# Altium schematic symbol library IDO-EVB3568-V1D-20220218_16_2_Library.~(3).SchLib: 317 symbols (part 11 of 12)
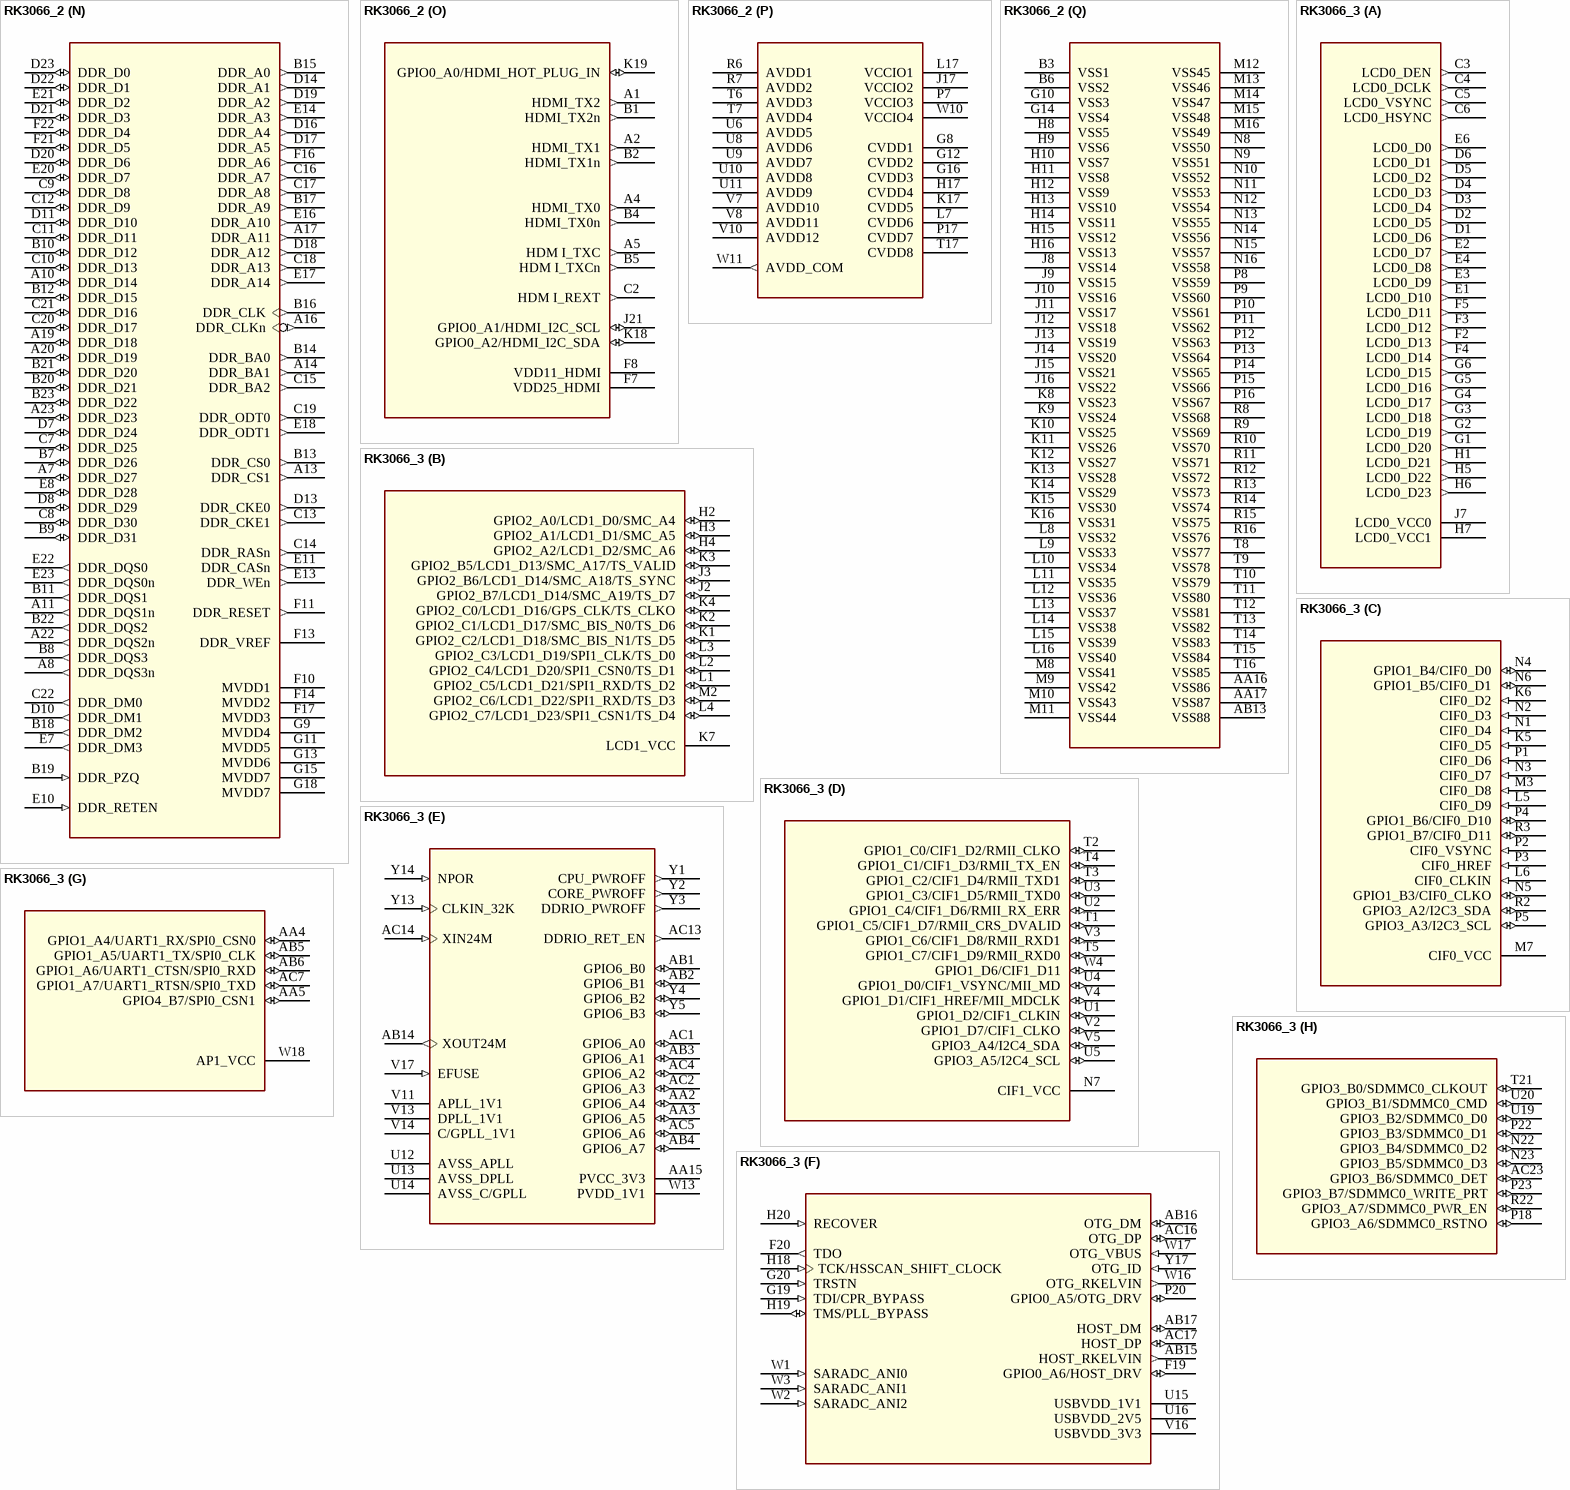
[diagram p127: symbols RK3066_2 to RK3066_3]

## RK3066_2
designator U?
Altium-Right: 120; Altium-Bottom: 230; Altium-Right1: 190; Altium-Bottom1: 200; Altium-Right2: 150; Altium-Bottom2: 250; Altium-Bottom3: 180; Altium-Right4: 160; Altium-Bottom5: 130; Altium-Bottom6: 280; Altium-Bottom7: 310; Altium-Bottom8: 270; Altium-Bottom9: 140; Altium-Bottom11: 530; Altium-Right13: 110; Altium-Bottom13: 170; Altium-Right14: 100; Altium-Bottom14: 470; Altium-Right15: 80; Altium-Bottom15: 350
footprint BGA453
part A pins: C3 LCD0_DEN (out), C4 LCD0_DCLK (out), C5 LCD0_VSYNC (out), C6 LCD0_HSYNC (out), D1 LCD0_D6 (out), D2 LCD0_D5 (out), D3 LCD0_D4 (out), D4 LCD0_D3 (out), D5 LCD0_D2 (out), D6 LCD0_D1 (out), E1 LCD0_D10 (out), E2 LCD0_D7 (out), E3 LCD0_D9 (out), E4 LCD0_D8 (out), E6 LCD0_D0 (out), F2 LCD0_D13 (out), F3 LCD0_D12 (out), F4 LCD0_D14 (out), F5 LCD0_D11 (out), G1 LCD0_D20 (out), G2 LCD0_D19 (out), G3 LCD0_D18 (out), G4 LCD0_D17 (out), G5 LCD0_D16 (out), G6 LCD0_D15 (out), H1 LCD0_D21 (out), H5 LCD0_D22 (out), H6 LCD0_D23 (out), H7 LCD0_VCC1 (power), J7 LCD0_VCC0 (power)
part B pins: H2 GPIO2_A0/LCD1_D0/SMC_A4 (io), H3 GPIO2_A1/LCD1_D1/SMC_A5 (io), H4 GPIO2_A2/LCD1_D2/SMC_A6 (io), J2 GPIO2_B7/LCD1_D14/SMC_A19/TS_D7 (io), J3 GPIO2_B6/LCD1_D14/SMC_A18/TS_SYNC (io), K1 GPIO2_C2/LCD1_D18/SMC_BIS_N1/TS_D5 (io), K2 GPIO2_C1/LCD1_D17/SMC_BIS_N0/TS_D6 (io), K3 GPIO2_B5/LCD1_D13/SMC_A17/TS_VALID (io), K4 GPIO2_C0/LCD1_D16/GPS_CLK/TS_CLKO (io), K7 LCD1_VCC (power), L1 GPIO2_C5/LCD1_D21/SPI1_RXD/TS_D2 (io), L2 GPIO2_C4/LCD1_D20/SPI1_CSN0/TS_D1 (io), L3 GPIO2_C3/LCD1_D19/SPI1_CLK/TS_D0 (io), L4 GPIO2_C7/LCD1_D23/SPI1_CSN1/TS_D4 (io), M2 GPIO2_C6/LCD1_D22/SPI1_RXD/TS_D3 (io)
part C pins: K5 CIF0_D5 (in), K6 CIF0_D2 (in), L5 CIF0_D9 (in), L6 CIF0_CLKIN (in), M3 CIF0_D8 (in), M7 CIF0_VCC (power), N1 CIF0_D4 (in), N2 CIF0_D3 (in), N3 CIF0_D7 (in), N4 GPIO1_B4/CIF0_D0 (io), N5 GPIO1_B3/CIF0_CLKO (io), N6 GPIO1_B5/CIF0_D1 (io), P1 CIF0_D6 (in), P2 CIF0_VSYNC (in), P3 CIF0_HREF (in), P4 GPIO1_B6/CIF0_D10 (io), P5 GPIO3_A3/I2C3_SCL (io), R2 GPIO3_A2/I2C3_SDA (io), R3 GPIO1_B7/CIF0_D11 (io)
part D pins: N7 CIF1_VCC (power), T1 GPIO1_C5/CIF1_D7/RMII_CRS_DVALID (io), T2 GPIO1_C0/CIF1_D2/RMII_CLKO (io), T3 GPIO1_C2/CIF1_D4/RMII_TXD1 (io), T4 GPIO1_C1/CIF1_D3/RMII_TX_EN (io), T5 GPIO1_C7/CIF1_D9/RMII_RXD0 (io), U1 GPIO1_D2/CIF1_CLKIN (io), U2 GPIO1_C4/CIF1_D6/RMII_RX_ERR (io), U3 GPIO1_C3/CIF1_D5/RMII_TXD0 (io), U4 GPIO1_D0/CIF1_VSYNC/MII_MD (io), U5 GPIO3_A5/I2C4_SCL (io), V2 GPIO1_D7/CIF1_CLKO (io), V3 GPIO1_C6/CIF1_D8/RMII_RXD1 (io), V4 GPIO1_D1/CIF1_HREF/MII_MDCLK (io), V5 GPIO3_A4/I2C4_SDA (io), W4 GPIO1_D6/CIF1_D11 (io)
part E pins: AA2 GPIO6_A4 (io), AA3 GPIO6_A5 (io), AA15 PVCC_3V3 (power), AB1 GPIO6_B0 (io), AB2 GPIO6_B1 (io), AB3 GPIO6_A1 (io), AB4 GPIO6_A7 (io), AB14 XOUT24M (out), AC1 GPIO6_A0 (io), AC2 GPIO6_A3 (io), AC4 GPIO6_A2 (io), AC5 GPIO6_A6 (io), AC13 DDRIO_RET_EN (out), AC14 XIN24M (in), U12 AVSS_APLL (power), U13 AVSS_DPLL (power), U14 AVSS_C/GPLL (power), V11 APLL_1V1 (power), V13 DPLL_1V1 (power), V14 C/GPLL_1V1 (power), V17 EFUSE (in), W13 PVDD_1V1 (power), Y1 CPU_PWROFF (out), Y2 CORE_PWROFF (out), Y3 DDRIO_PWROFF (out), Y4 GPIO6_B2 (io), Y5 GPIO6_B3 (io), Y13 CLKIN_32K (in), Y14 NPOR (in)
part F pins: AB15 HOST_RKELVIN (out), AB16 OTG_DM (io), AB17 HOST_DM (io), AC16 OTG_DP (io), AC17 HOST_DP (io), F19 GPIO0_A6/HOST_DRV (io), F20 TDO (out), G19 TDI/CPR_BYPASS (in), G20 TRSTN (in), H18 TCK/HSSCAN_SHIFT_CLOCK (in), H19 TMS/PLL_BYPASS (io), H20 RECOVER (in), P20 GPIO0_A5/OTG_DRV (io), U15 USBVDD_1V1 (power), U16 USBVDD_2V5 (power), V16 USBVDD_3V3 (power), W1 SARADC_ANI0 (in), W2 SARADC_ANI2 (in), W3 SARADC_ANI1 (in), W16 OTG_RKELVIN (out), W17 OTG_VBUS (in), Y17 OTG_ID (in)
part G pins: AA4 GPIO1_A4/UART1_RX/SPI0_CSN0 (io), AA5 GPIO4_B7/SPI0_CSN1 (io), AB5 GPIO1_A5/UART1_TX/SPI0_CLK (io), AB6 GPIO1_A6/UART1_CTSN/SPI0_RXD (io), AC7 GPIO1_A7/UART1_RTSN/SPI0_TXD (io), W18 AP1_VCC (power)
part H pins: AC23 GPIO3_B6/SDMMC0_DET (io), N22 GPIO3_B4/SDMMC0_D2 (io), N23 GPIO3_B5/SDMMC0_D3 (io), P18 GPIO3_A6/SDMMC0_RSTNO (io), P22 GPIO3_B3/SDMMC0_D1 (io), P23 GPIO3_B7/SDMMC0_WRITE_PRT (io), R22 GPIO3_A7/SDMMC0_PWR_EN (io), T21 GPIO3_B0/SDMMC0_CLKOUT (io), U19 GPIO3_B2/SDMMC0_D0 (io), U20 GPIO3_B1/SDMMC0_CMD (io)
part I pins: AA6 GPIO3_C1/SDMMC1_D0 (io), AA7 GPIO3_C2/SDMMC1_D1 (io), AA8 GPIO3_C7/SDMMC1_WRITE_PRT (io), AA9 GPIO1_A1/UART0_SOUT (io), AA10 GPIO0_C3/I2S1_LRCK_TX (io), AA12 GPIO1_A0/UART0_SIN (io), AB7 GPIO3_C0/SDMMC1_CMD (io), AB8 GPIO3_D2/SDMMC1_INT (io), AB9 GPIO0_C1/I2S1_SCLK (io), AB10 GPIO3_D1/SDMMC1_BACKEND (io), AB11 GPIO1_A2/UART0_CTS (io), AC8 GPIO3_C4/SDMMC1_D3 (io), AC10 GPIO3_C3/SDMMC1_D2 (io), AC11 GPIO0_C2/I2S1_LRCK_RX (io), U18 AP0_VCC (io), W6 GPIO3_C6/SDMMC1_DET (io), W7 GPIO0_C4/I2S1_SDI (io), W8 GPIO1_A3/UART0_RTS (io), Y6 GPIO3_C5/SDMMC1_CLKO (io), Y7 GPIO3_D0/SDMMC1_PWR_EN (io), Y8 GPIO0_C5/I2S1_SDO (io), Y11 GPIO0_C0/I2S1_CLK (io)
part J pins: AA11 GPIO4_C0/SMC_D0/TRACE_D0 (io), AA13 GPIO4_C4/SMC_D4/TRACE_D4 (io), AA14 GPIO4_D0/SMC_D8/TRACE_D8 (io), AA18 GPIO4_D3/SMC_D11/TRACE_D11 (io), AA19 GPIO4_D1/SMC_D9/TRACE_D9 (io), AA20 GPIO4_D5/SMC_D13/TRACE_D13 (io), AA21 GPIO0_D5/I2S2_SDO/SMC_A1 (io), AA22 GPIO0_D4/I2S2_SDI/SMC_A0 (io), AB12 GPIO4_C6/SMC_D6/TRACE_D6 (io), AB18 GPIO4_C3/SMC_D3/TRACE_D3 (io), AB19 GPIO4_D6/SMC_D14/TRACE_D14 (io), AB20 GPIO0_C7/SMC_A3/TRACE_CTL (io), AB21 GPIO0_D2/I2S2_LRCK_RX/SMC_OEN (io), AB23 GPIO0_C6/SMC_A2/TRACE_CLK (io), AC19 GPIO4_D7/SMC_D15/TRACE_D15 (io), AC20 GPIO4_D4/SMC_D12/TRACE_D12 (io), AC22 GPIO0_D3/I2S2_LRCK_TX/SMC_ADVN (io), R17 SMC_VCC (power), W14 GPIO4_C7/SMC_D7/TRACE_D7 (io), Y10 GPIO4_C1/SMC_D1/TRACE_D1 (io), Y16 GPIO4_C2/SMC_D2/TRACE_D2 (io), Y18 GPIO4_C5/SMC_D5/TRACE_D5 (io), Y19 GPIO4_D2/SMC_D10/TRACE_D10 (io), Y20 GPIO0_D1/I2S2_SCLK/SMC_WEN (io), Y23 GPIO0_D0/I2S2_CLK/SMC_CSN0 (io)
part K pins: AB22 FLASH_D0/EMMC_D0 (io), M17 FLASH_VCC0 (power), N17 FLASH_VCC1 (power), T18 GPIO4_B0/FLASH_CS1 (io), T19 GPIO4_B1/FLASH_CS2/EMMC_CMD (io), T20 GPIO4_B2/FLASH_CS3/EMMC_RST (io), T22 FLASH_ALE (out), T23 FLASH_CS0 (out), U21 FLASH_WP/EMMC_PWR_EN (out), U22 FLASH_D7/EMMC_D7 (io), U23 FLASH_D6/EMMC_D6 (io), V19 FLASH_RDN (out), V20 FLASH_CLE (out), V21 FLASH_RDY (out), V22 FLASH_D5/EMMC_D5 (io), W20 FLASH_WRN (out), W21 GPIO3_D7/FLASH_DQS/EMMC_CLKO (io), W22 FLASH_D4/EMMC_D4 (io), W23 FLASH_D3/EMMC_D3 (io), Y21 FLASH_D1/EMMC_D1 (io), Y22 FLASH_D2/EMMC_D2 (io)
part L pins: L18 GPIO0_B4/I2S0_D0 (io), L19 GPIO0_B7/I2S0_D3 (io), L21 GPIO1_B2/SPDIF_TX (io), L22 GPIO0_B5/I2S0_D1 (io), N10 GPIO0_B2/I2S0_LRCK_RX (io), N18 GPIO0_B6/I2S0_D2 (io), N21 GPIO0_B1/I2S0_SCLK (io), P19 GPIO0_A7/I2S0_SDI (io), P21 GPIO0_B3/I2S0_LRCK_TX (io), R21 GPIO0_B0/I2S0_CLK (io)
part M pins: G21 GPIO0_A3/PWM0 (io), G22 GPIO0_D6/PWM2 (io), G23 GPIO0_A4/PWM1 (io), H21 GPIO0_D7/PWM3 (io), H22 GPIO3_A1/I2C2_SCL (io), H23 GPIO2_D4/I2C0_SDA (io), J22 GPIO2_D5/I2C0_SCL (io), K20 GPIO3_D6/UART3_RTS (io), K21 GPIO3_D4/UART3_SOUT (io), K22 GPIO3_D3/UART3_SIN (io), K23 GPIO2_D6/I2C1_SDA (io), L20 GPIO3_D5/UART3_CTS (io), L23 GPIO1_B1/UART2_SOUT (io), M11 GPIO2_D7/I2C1_SCL (io), M22 GPIO1_B0/UART2_SIN (io), N19 GPIO3_A0/I2C2_SDA (io)
part N pins: A7 DDR_D27 (io), A8 DDR_DQS3n (out), A10 DDR_D14 (io), A11 DDR_DQS1n (out), A13 DDR_CS1 (out), A14 DDR_BA1 (out), A16 DDR_CLKn (out), A17 DDR_A11 (out), A19 DDR_D18 (io), A20 DDR_D19 (io), A22 DDR_DQS2n (out), A23 DDR_D23 (io), B7 DDR_D26 (io), B8 DDR_DQS3 (out), B9 DDR_D31 (io), B10 DDR_D12 (io), B11 DDR_DQS1 (out), B12 DDR_D15 (io), B13 DDR_CS0 (out), B14 DDR_BA0 (out), B15 DDR_A0 (out), B16 DDR_CLK (out), B17 DDR_A9 (out), B18 DDR_DM2 (out), B19 DDR_PZQ (in), B20 DDR_D21 (io), B21 DDR_D20 (io), B22 DDR_DQS2 (out), B23 DDR_D22 (io), C7 DDR_D25 (io), C8 DDR_D30 (io), C9 DDR_D8 (io), C10 DDR_D13 (io), C11 DDR_D11 (io), C12 DDR_D9 (io), C13 DDR_CKE1 (out), C14 DDR_RASn (out), C15 DDR_BA2 (out), C16 DDR_A7 (out), C17 DDR_A8 (out), C18 DDR_A13 (out), C19 DDR_ODT0 (out), C20 DDR_D17 (io), C21 DDR_D16 (io), C22 DDR_DM0 (out), D7 DDR_D24 (io), D8 DDR_D29 (io), D10 DDR_DM1 (out), D11 DDR_D10 (io), D13 DDR_CKE0 (out), D14 DDR_A1 (out), D16 DDR_A4 (out), D17 DDR_A5 (out), D18 DDR_A12 (out), D19 DDR_A2 (out), D20 DDR_D6 (io), D21 DDR_D3 (io), D22 DDR_D1 (io), D23 DDR_D0 (io), E7 DDR_DM3 (out), E8 DDR_D28 (io), E10 DDR_RETEN (in), E11 DDR_CASn (out), E13 DDR_WEn (out), E14 DDR_A3 (out), E16 DDR_A10 (out), E17 DDR_A14 (out), E18 DDR_ODT1 (out), E20 DDR_D7 (io), E21 DDR_D2 (io), E22 DDR_DQS0 (out), E23 DDR_DQS0n (out), F10 MVDD1 (power), F11 DDR_RESET (out), F13 DDR_VREF (power), F14 MVDD2 (power), F16 DDR_A6 (out), F17 MVDD3 (power), F21 DDR_D5 (io), F22 DDR_D4 (io), G9 MVDD4 (power), G11 MVDD5 (power), G13 MVDD6 (power), G15 MVDD7 (power), G18 MVDD7 (power)
part O pins: A1 HDMI_TX2 (out), A2 HDMI_TX1 (out), A4 HDMI_TX0 (out), A5 HDM I_TXC (out), B1 HDMI_TX2n (out), B2 HDMI_TX1n (out), B4 HDMI_TX0n (out), B5 HDM I_TXCn (out), C2 HDM I_REXT (out), F7 VDD25_HDMI (power), F8 VDD11_HDMI (power), J21 GPIO0_A1/HDMI_I2C_SCL (io), K18 GPIO0_A2/HDMI_I2C_SDA (io), K19 GPIO0_A0/HDMI_HOT_PLUG_IN (io)
part P pins: G8 CVDD1 (power), G12 CVDD2 (power), G16 CVDD3 (power), H17 CVDD4 (power), J17 VCCIO2 (power), K17 CVDD5 (power), L7 CVDD6 (power), L17 VCCIO1 (power), P7 VCCIO3 (power), P17 CVDD7 (power), R6 AVDD1 (power), R7 AVDD2 (power), T6 AVDD3 (power), T7 AVDD4 (power), T17 CVDD8 (power), U6 AVDD5 (power), U8 AVDD6 (power), U9 AVDD7 (power), U10 AVDD8 (power), U11 AVDD9 (power), V7 AVDD10 (power), V8 AVDD11 (power), V10 AVDD12 (power), W10 VCCIO4 (power), W11 AVDD_COM (out)
part Q pins: AA16 VSS86 (power), AA17 VSS87 (power), AB13 VSS88 (power), B3 VSS1 (power), B6 VSS2 (power), G10 VSS3 (power), G14 VSS4 (power), H8 VSS5 (power), H9 VSS6 (power), H10 VSS7 (power), H11 VSS8 (power), H12 VSS9 (power), H13 VSS10 (power), H14 VSS11 (power), H15 VSS12 (power), H16 VSS13 (power), J8 VSS14 (power), J9 VSS15 (power), J10 VSS16 (power), J11 VSS17 (power), J12 VSS18 (power), J13 VSS19 (power), J14 VSS20 (power), J15 VSS21 (power), J16 VSS22 (power), K8 VSS23 (power), K9 VSS24 (power), K10 VSS25 (power), K11 VSS26 (power), K12 VSS27 (power), K13 VSS28 (power), K14 VSS29 (power), K15 VSS30 (power), K16 VSS31 (power), L8 VSS32 (power), L9 VSS33 (power), L10 VSS34 (power), L11 VSS35 (power), L12 VSS36 (power), L13 VSS37 (power), L14 VSS38 (power), L15 VSS39 (power), L16 VSS40 (power), M8 VSS41 (power), M9 VSS42 (power), M10 VSS43 (power), M11 VSS44 (power), M12 VSS45 (power), M13 VSS46 (power), M14 VSS47 (power), M15 VSS48 (power), M16 VSS49 (power), N8 VSS50 (power), N9 VSS51 (power), N10 VSS52 (power), N11 VSS53 (power), N12 VSS54 (power), N13 VSS55 (power), N14 VSS56 (power), N15 VSS57 (power), N16 VSS58 (power), P8 VSS59 (power), P9 VSS60 (power), P10 VSS61 (power), P11 VSS62 (power), P12 VSS63 (power), P13 VSS64 (power), P14 VSS65 (power), P15 VSS66 (power), P16 VSS67 (power), R8 VSS68 (power), R9 VSS69 (power), R10 VSS70 (power), R11 VSS71 (power), R12 VSS72 (power), R13 VSS73 (power), R14 VSS74 (power), R15 VSS75 (power), R16 VSS76 (power), T8 VSS77 (power), T9 VSS78 (power), T10 VSS79 (power), T11 VSS80 (power), T12 VSS81 (power), T13 VSS82 (power), T14 VSS83 (power), T15 VSS84 (power), T16 VSS85 (power)

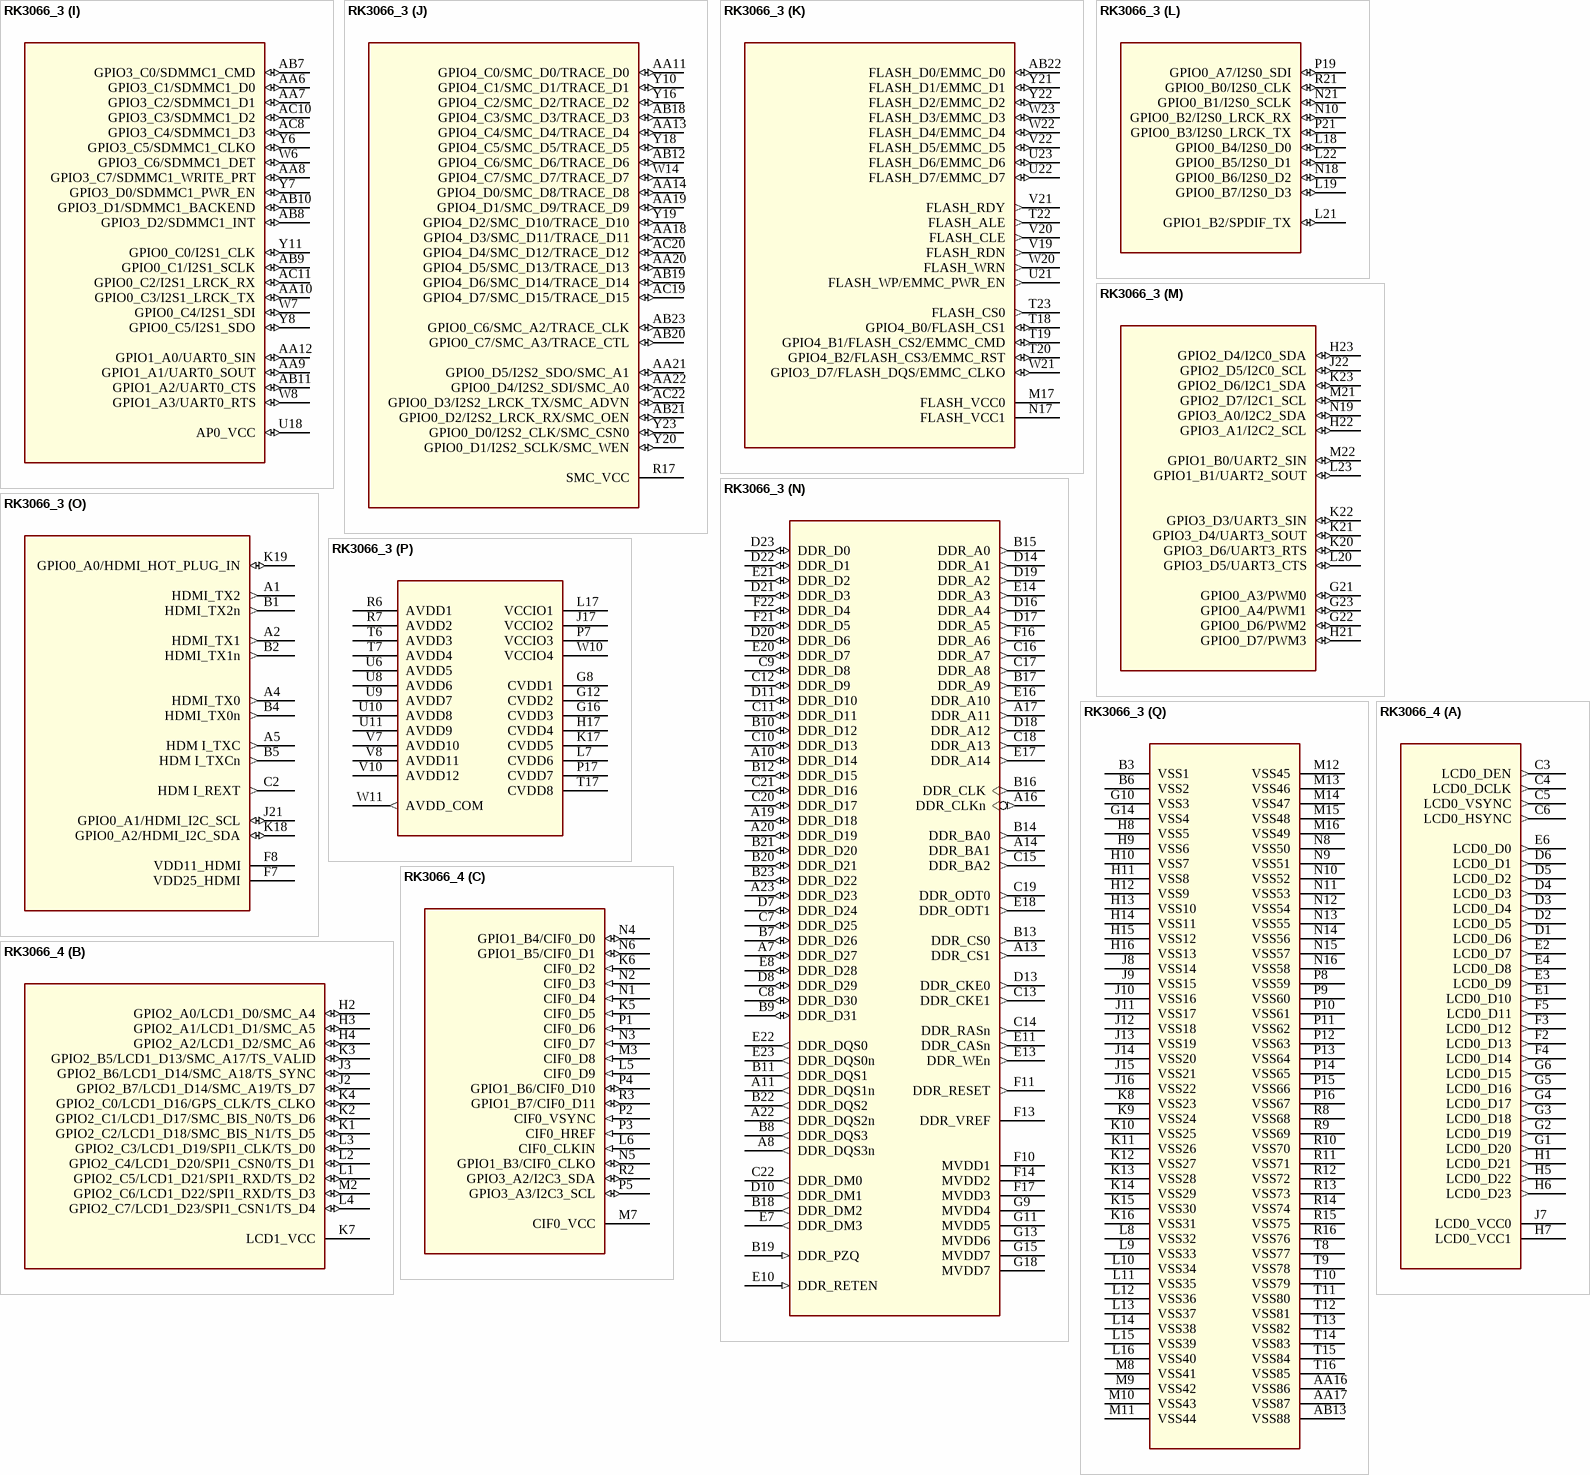
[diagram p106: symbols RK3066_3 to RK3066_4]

## RK3066_3
designator U?
Altium-Right: 190; Altium-Bottom: 200; Altium-Right1: 150; Altium-Bottom1: 250; Altium-Right2: 230; Altium-Bottom2: 180; Altium-Right3: 160; Altium-Bottom3: 120; Altium-Bottom4: 130; Altium-Bottom5: 280; Altium-Bottom6: 310; Altium-Bottom7: 270; Altium-Bottom8: 140; Altium-Bottom10: 530; Altium-Right12: 110; Altium-Bottom12: 170; Altium-Right13: 100; Altium-Bottom13: 470; Altium-Right14: 80; Altium-Bottom14: 350
footprint BGA453
part A pins: C3 LCD0_DEN (out), C4 LCD0_DCLK (out), C5 LCD0_VSYNC (out), C6 LCD0_HSYNC (out), D1 LCD0_D6 (out), D2 LCD0_D5 (out), D3 LCD0_D4 (out), D4 LCD0_D3 (out), D5 LCD0_D2 (out), D6 LCD0_D1 (out), E1 LCD0_D10 (out), E2 LCD0_D7 (out), E3 LCD0_D9 (out), E4 LCD0_D8 (out), E6 LCD0_D0 (out), F2 LCD0_D13 (out), F3 LCD0_D12 (out), F4 LCD0_D14 (out), F5 LCD0_D11 (out), G1 LCD0_D20 (out), G2 LCD0_D19 (out), G3 LCD0_D18 (out), G4 LCD0_D17 (out), G5 LCD0_D16 (out), G6 LCD0_D15 (out), H1 LCD0_D21 (out), H5 LCD0_D22 (out), H6 LCD0_D23 (out), H7 LCD0_VCC1 (power), J7 LCD0_VCC0 (power)
part B pins: H2 GPIO2_A0/LCD1_D0/SMC_A4 (io), H3 GPIO2_A1/LCD1_D1/SMC_A5 (io), H4 GPIO2_A2/LCD1_D2/SMC_A6 (io), J2 GPIO2_B7/LCD1_D14/SMC_A19/TS_D7 (io), J3 GPIO2_B6/LCD1_D14/SMC_A18/TS_SYNC (io), K1 GPIO2_C2/LCD1_D18/SMC_BIS_N1/TS_D5 (io), K2 GPIO2_C1/LCD1_D17/SMC_BIS_N0/TS_D6 (io), K3 GPIO2_B5/LCD1_D13/SMC_A17/TS_VALID (io), K4 GPIO2_C0/LCD1_D16/GPS_CLK/TS_CLKO (io), K7 LCD1_VCC (power), L1 GPIO2_C5/LCD1_D21/SPI1_RXD/TS_D2 (io), L2 GPIO2_C4/LCD1_D20/SPI1_CSN0/TS_D1 (io), L3 GPIO2_C3/LCD1_D19/SPI1_CLK/TS_D0 (io), L4 GPIO2_C7/LCD1_D23/SPI1_CSN1/TS_D4 (io), M2 GPIO2_C6/LCD1_D22/SPI1_RXD/TS_D3 (io)
part C pins: K5 CIF0_D5 (in), K6 CIF0_D2 (in), L5 CIF0_D9 (in), L6 CIF0_CLKIN (in), M3 CIF0_D8 (in), M7 CIF0_VCC (power), N1 CIF0_D4 (in), N2 CIF0_D3 (in), N3 CIF0_D7 (in), N4 GPIO1_B4/CIF0_D0 (io), N5 GPIO1_B3/CIF0_CLKO (io), N6 GPIO1_B5/CIF0_D1 (io), P1 CIF0_D6 (in), P2 CIF0_VSYNC (in), P3 CIF0_HREF (in), P4 GPIO1_B6/CIF0_D10 (io), P5 GPIO3_A3/I2C3_SCL (io), R2 GPIO3_A2/I2C3_SDA (io), R3 GPIO1_B7/CIF0_D11 (io)
part D pins: N7 CIF1_VCC (power), T1 GPIO1_C5/CIF1_D7/RMII_CRS_DVALID (io), T2 GPIO1_C0/CIF1_D2/RMII_CLKO (io), T3 GPIO1_C2/CIF1_D4/RMII_TXD1 (io), T4 GPIO1_C1/CIF1_D3/RMII_TX_EN (io), T5 GPIO1_C7/CIF1_D9/RMII_RXD0 (io), U1 GPIO1_D2/CIF1_CLKIN (io), U2 GPIO1_C4/CIF1_D6/RMII_RX_ERR (io), U3 GPIO1_C3/CIF1_D5/RMII_TXD0 (io), U4 GPIO1_D0/CIF1_VSYNC/MII_MD (io), U5 GPIO3_A5/I2C4_SCL (io), V2 GPIO1_D7/CIF1_CLKO (io), V3 GPIO1_C6/CIF1_D8/RMII_RXD1 (io), V4 GPIO1_D1/CIF1_HREF/MII_MDCLK (io), V5 GPIO3_A4/I2C4_SDA (io), W4 GPIO1_D6/CIF1_D11 (io)
part E pins: AA2 GPIO6_A4 (io), AA3 GPIO6_A5 (io), AA15 PVCC_3V3 (power), AB1 GPIO6_B0 (io), AB2 GPIO6_B1 (io), AB3 GPIO6_A1 (io), AB4 GPIO6_A7 (io), AB14 XOUT24M (out), AC1 GPIO6_A0 (io), AC2 GPIO6_A3 (io), AC4 GPIO6_A2 (io), AC5 GPIO6_A6 (io), AC13 DDRIO_RET_EN (out), AC14 XIN24M (in), U12 AVSS_APLL (power), U13 AVSS_DPLL (power), U14 AVSS_C/GPLL (power), V11 APLL_1V1 (power), V13 DPLL_1V1 (power), V14 C/GPLL_1V1 (power), V17 EFUSE (in), W13 PVDD_1V1 (power), Y1 CPU_PWROFF (out), Y2 CORE_PWROFF (out), Y3 DDRIO_PWROFF (out), Y4 GPIO6_B2 (io), Y5 GPIO6_B3 (io), Y13 CLKIN_32K (in), Y14 NPOR (in)
part F pins: AB15 HOST_RKELVIN (out), AB16 OTG_DM (io), AB17 HOST_DM (io), AC16 OTG_DP (io), AC17 HOST_DP (io), F19 GPIO0_A6/HOST_DRV (io), F20 TDO (out), G19 TDI/CPR_BYPASS (in), G20 TRSTN (in), H18 TCK/HSSCAN_SHIFT_CLOCK (in), H19 TMS/PLL_BYPASS (io), H20 RECOVER (in), P20 GPIO0_A5/OTG_DRV (io), U15 USBVDD_1V1 (power), U16 USBVDD_2V5 (power), V16 USBVDD_3V3 (power), W1 SARADC_ANI0 (in), W2 SARADC_ANI2 (in), W3 SARADC_ANI1 (in), W16 OTG_RKELVIN (out), W17 OTG_VBUS (in), Y17 OTG_ID (in)
part G pins: AA4 GPIO1_A4/UART1_RX/SPI0_CSN0 (io), AA5 GPIO4_B7/SPI0_CSN1 (io), AB5 GPIO1_A5/UART1_TX/SPI0_CLK (io), AB6 GPIO1_A6/UART1_CTSN/SPI0_RXD (io), AC7 GPIO1_A7/UART1_RTSN/SPI0_TXD (io), W18 AP1_VCC (power)
part H pins: AC23 GPIO3_B6/SDMMC0_DET (io), N22 GPIO3_B4/SDMMC0_D2 (io), N23 GPIO3_B5/SDMMC0_D3 (io), P18 GPIO3_A6/SDMMC0_RSTNO (io), P22 GPIO3_B3/SDMMC0_D1 (io), P23 GPIO3_B7/SDMMC0_WRITE_PRT (io), R22 GPIO3_A7/SDMMC0_PWR_EN (io), T21 GPIO3_B0/SDMMC0_CLKOUT (io), U19 GPIO3_B2/SDMMC0_D0 (io), U20 GPIO3_B1/SDMMC0_CMD (io)
part I pins: AA6 GPIO3_C1/SDMMC1_D0 (io), AA7 GPIO3_C2/SDMMC1_D1 (io), AA8 GPIO3_C7/SDMMC1_WRITE_PRT (io), AA9 GPIO1_A1/UART0_SOUT (io), AA10 GPIO0_C3/I2S1_LRCK_TX (io), AA12 GPIO1_A0/UART0_SIN (io), AB7 GPIO3_C0/SDMMC1_CMD (io), AB8 GPIO3_D2/SDMMC1_INT (io), AB9 GPIO0_C1/I2S1_SCLK (io), AB10 GPIO3_D1/SDMMC1_BACKEND (io), AB11 GPIO1_A2/UART0_CTS (io), AC8 GPIO3_C4/SDMMC1_D3 (io), AC10 GPIO3_C3/SDMMC1_D2 (io), AC11 GPIO0_C2/I2S1_LRCK_RX (io), U18 AP0_VCC (io), W6 GPIO3_C6/SDMMC1_DET (io), W7 GPIO0_C4/I2S1_SDI (io), W8 GPIO1_A3/UART0_RTS (io), Y6 GPIO3_C5/SDMMC1_CLKO (io), Y7 GPIO3_D0/SDMMC1_PWR_EN (io), Y8 GPIO0_C5/I2S1_SDO (io), Y11 GPIO0_C0/I2S1_CLK (io)
part J pins: AA11 GPIO4_C0/SMC_D0/TRACE_D0 (io), AA13 GPIO4_C4/SMC_D4/TRACE_D4 (io), AA14 GPIO4_D0/SMC_D8/TRACE_D8 (io), AA18 GPIO4_D3/SMC_D11/TRACE_D11 (io), AA19 GPIO4_D1/SMC_D9/TRACE_D9 (io), AA20 GPIO4_D5/SMC_D13/TRACE_D13 (io), AA21 GPIO0_D5/I2S2_SDO/SMC_A1 (io), AA22 GPIO0_D4/I2S2_SDI/SMC_A0 (io), AB12 GPIO4_C6/SMC_D6/TRACE_D6 (io), AB18 GPIO4_C3/SMC_D3/TRACE_D3 (io), AB19 GPIO4_D6/SMC_D14/TRACE_D14 (io), AB20 GPIO0_C7/SMC_A3/TRACE_CTL (io), AB21 GPIO0_D2/I2S2_LRCK_RX/SMC_OEN (io), AB23 GPIO0_C6/SMC_A2/TRACE_CLK (io), AC19 GPIO4_D7/SMC_D15/TRACE_D15 (io), AC20 GPIO4_D4/SMC_D12/TRACE_D12 (io), AC22 GPIO0_D3/I2S2_LRCK_TX/SMC_ADVN (io), R17 SMC_VCC (power), W14 GPIO4_C7/SMC_D7/TRACE_D7 (io), Y10 GPIO4_C1/SMC_D1/TRACE_D1 (io), Y16 GPIO4_C2/SMC_D2/TRACE_D2 (io), Y18 GPIO4_C5/SMC_D5/TRACE_D5 (io), Y19 GPIO4_D2/SMC_D10/TRACE_D10 (io), Y20 GPIO0_D1/I2S2_SCLK/SMC_WEN (io), Y23 GPIO0_D0/I2S2_CLK/SMC_CSN0 (io)
part K pins: AB22 FLASH_D0/EMMC_D0 (io), M17 FLASH_VCC0 (power), N17 FLASH_VCC1 (power), T18 GPIO4_B0/FLASH_CS1 (io), T19 GPIO4_B1/FLASH_CS2/EMMC_CMD (io), T20 GPIO4_B2/FLASH_CS3/EMMC_RST (io), T22 FLASH_ALE (out), T23 FLASH_CS0 (out), U21 FLASH_WP/EMMC_PWR_EN (out), U22 FLASH_D7/EMMC_D7 (io), U23 FLASH_D6/EMMC_D6 (io), V19 FLASH_RDN (out), V20 FLASH_CLE (out), V21 FLASH_RDY (out), V22 FLASH_D5/EMMC_D5 (io), W20 FLASH_WRN (out), W21 GPIO3_D7/FLASH_DQS/EMMC_CLKO (io), W22 FLASH_D4/EMMC_D4 (io), W23 FLASH_D3/EMMC_D3 (io), Y21 FLASH_D1/EMMC_D1 (io), Y22 FLASH_D2/EMMC_D2 (io)
part L pins: L18 GPIO0_B4/I2S0_D0 (io), L19 GPIO0_B7/I2S0_D3 (io), L21 GPIO1_B2/SPDIF_TX (io), L22 GPIO0_B5/I2S0_D1 (io), N10 GPIO0_B2/I2S0_LRCK_RX (io), N18 GPIO0_B6/I2S0_D2 (io), N21 GPIO0_B1/I2S0_SCLK (io), P19 GPIO0_A7/I2S0_SDI (io), P21 GPIO0_B3/I2S0_LRCK_TX (io), R21 GPIO0_B0/I2S0_CLK (io)
part M pins: G21 GPIO0_A3/PWM0 (io), G22 GPIO0_D6/PWM2 (io), G23 GPIO0_A4/PWM1 (io), H21 GPIO0_D7/PWM3 (io), H22 GPIO3_A1/I2C2_SCL (io), H23 GPIO2_D4/I2C0_SDA (io), J22 GPIO2_D5/I2C0_SCL (io), K20 GPIO3_D6/UART3_RTS (io), K21 GPIO3_D4/UART3_SOUT (io), K22 GPIO3_D3/UART3_SIN (io), K23 GPIO2_D6/I2C1_SDA (io), L20 GPIO3_D5/UART3_CTS (io), L23 GPIO1_B1/UART2_SOUT (io), M21 GPIO2_D7/I2C1_SCL (io), M22 GPIO1_B0/UART2_SIN (io), N19 GPIO3_A0/I2C2_SDA (io)
part N pins: A7 DDR_D27 (io), A8 DDR_DQS3n (out), A10 DDR_D14 (io), A11 DDR_DQS1n (out), A13 DDR_CS1 (out), A14 DDR_BA1 (out), A16 DDR_CLKn (out), A17 DDR_A11 (out), A19 DDR_D18 (io), A20 DDR_D19 (io), A22 DDR_DQS2n (out), A23 DDR_D23 (io), B7 DDR_D26 (io), B8 DDR_DQS3 (out), B9 DDR_D31 (io), B10 DDR_D12 (io), B11 DDR_DQS1 (out), B12 DDR_D15 (io), B13 DDR_CS0 (out), B14 DDR_BA0 (out), B15 DDR_A0 (out), B16 DDR_CLK (out), B17 DDR_A9 (out), B18 DDR_DM2 (out), B19 DDR_PZQ (in), B20 DDR_D21 (io), B21 DDR_D20 (io), B22 DDR_DQS2 (out), B23 DDR_D22 (io), C7 DDR_D25 (io), C8 DDR_D30 (io), C9 DDR_D8 (io), C10 DDR_D13 (io), C11 DDR_D11 (io), C12 DDR_D9 (io), C13 DDR_CKE1 (out), C14 DDR_RASn (out), C15 DDR_BA2 (out), C16 DDR_A7 (out), C17 DDR_A8 (out), C18 DDR_A13 (out), C19 DDR_ODT0 (out), C20 DDR_D17 (io), C21 DDR_D16 (io), C22 DDR_DM0 (out), D7 DDR_D24 (io), D8 DDR_D29 (io), D10 DDR_DM1 (out), D11 DDR_D10 (io), D13 DDR_CKE0 (out), D14 DDR_A1 (out), D16 DDR_A4 (out), D17 DDR_A5 (out), D18 DDR_A12 (out), D19 DDR_A2 (out), D20 DDR_D6 (io), D21 DDR_D3 (io), D22 DDR_D1 (io), D23 DDR_D0 (io), E7 DDR_DM3 (out), E8 DDR_D28 (io), E10 DDR_RETEN (in), E11 DDR_CASn (out), E13 DDR_WEn (out), E14 DDR_A3 (out), E16 DDR_A10 (out), E17 DDR_A14 (out), E18 DDR_ODT1 (out), E20 DDR_D7 (io), E21 DDR_D2 (io), E22 DDR_DQS0 (out), E23 DDR_DQS0n (out), F10 MVDD1 (power), F11 DDR_RESET (out), F13 DDR_VREF (power), F14 MVDD2 (power), F16 DDR_A6 (out), F17 MVDD3 (power), F21 DDR_D5 (io), F22 DDR_D4 (io), G9 MVDD4 (power), G11 MVDD5 (power), G13 MVDD6 (power), G15 MVDD7 (power), G18 MVDD7 (power)
part O pins: A1 HDMI_TX2 (out), A2 HDMI_TX1 (out), A4 HDMI_TX0 (out), A5 HDM I_TXC (out), B1 HDMI_TX2n (out), B2 HDMI_TX1n (out), B4 HDMI_TX0n (out), B5 HDM I_TXCn (out), C2 HDM I_REXT (out), F7 VDD25_HDMI (power), F8 VDD11_HDMI (power), J21 GPIO0_A1/HDMI_I2C_SCL (io), K18 GPIO0_A2/HDMI_I2C_SDA (io), K19 GPIO0_A0/HDMI_HOT_PLUG_IN (io)
part P pins: G8 CVDD1 (power), G12 CVDD2 (power), G16 CVDD3 (power), H17 CVDD4 (power), J17 VCCIO2 (power), K17 CVDD5 (power), L7 CVDD6 (power), L17 VCCIO1 (power), P7 VCCIO3 (power), P17 CVDD7 (power), R6 AVDD1 (power), R7 AVDD2 (power), T6 AVDD3 (power), T7 AVDD4 (power), T17 CVDD8 (power), U6 AVDD5 (power), U8 AVDD6 (power), U9 AVDD7 (power), U10 AVDD8 (power), U11 AVDD9 (power), V7 AVDD10 (power), V8 AVDD11 (power), V10 AVDD12 (power), W10 VCCIO4 (power), W11 AVDD_COM (out)
part Q pins: AA16 VSS86 (power), AA17 VSS87 (power), AB13 VSS88 (power), B3 VSS1 (power), B6 VSS2 (power), G10 VSS3 (power), G14 VSS4 (power), H8 VSS5 (power), H9 VSS6 (power), H10 VSS7 (power), H11 VSS8 (power), H12 VSS9 (power), H13 VSS10 (power), H14 VSS11 (power), H15 VSS12 (power), H16 VSS13 (power), J8 VSS14 (power), J9 VSS15 (power), J10 VSS16 (power), J11 VSS17 (power), J12 VSS18 (power), J13 VSS19 (power), J14 VSS20 (power), J15 VSS21 (power), J16 VSS22 (power), K8 VSS23 (power), K9 VSS24 (power), K10 VSS25 (power), K11 VSS26 (power), K12 VSS27 (power), K13 VSS28 (power), K14 VSS29 (power), K15 VSS30 (power), K16 VSS31 (power), L8 VSS32 (power), L9 VSS33 (power), L10 VSS34 (power), L11 VSS35 (power), L12 VSS36 (power), L13 VSS37 (power), L14 VSS38 (power), L15 VSS39 (power), L16 VSS40 (power), M8 VSS41 (power), M9 VSS42 (power), M10 VSS43 (power), M11 VSS44 (power), M12 VSS45 (power), M13 VSS46 (power), M14 VSS47 (power), M15 VSS48 (power), M16 VSS49 (power), N8 VSS50 (power), N9 VSS51 (power), N10 VSS52 (power), N11 VSS53 (power), N12 VSS54 (power), N13 VSS55 (power), N14 VSS56 (power), N15 VSS57 (power), N16 VSS58 (power), P8 VSS59 (power), P9 VSS60 (power), P10 VSS61 (power), P11 VSS62 (power), P12 VSS63 (power), P13 VSS64 (power), P14 VSS65 (power), P15 VSS66 (power), P16 VSS67 (power), R8 VSS68 (power), R9 VSS69 (power), R10 VSS70 (power), R11 VSS71 (power), R12 VSS72 (power), R13 VSS73 (power), R14 VSS74 (power), R15 VSS75 (power), R16 VSS76 (power), T8 VSS77 (power), T9 VSS78 (power), T10 VSS79 (power), T11 VSS80 (power), T12 VSS81 (power), T13 VSS82 (power), T14 VSS83 (power), T15 VSS84 (power), T16 VSS85 (power)

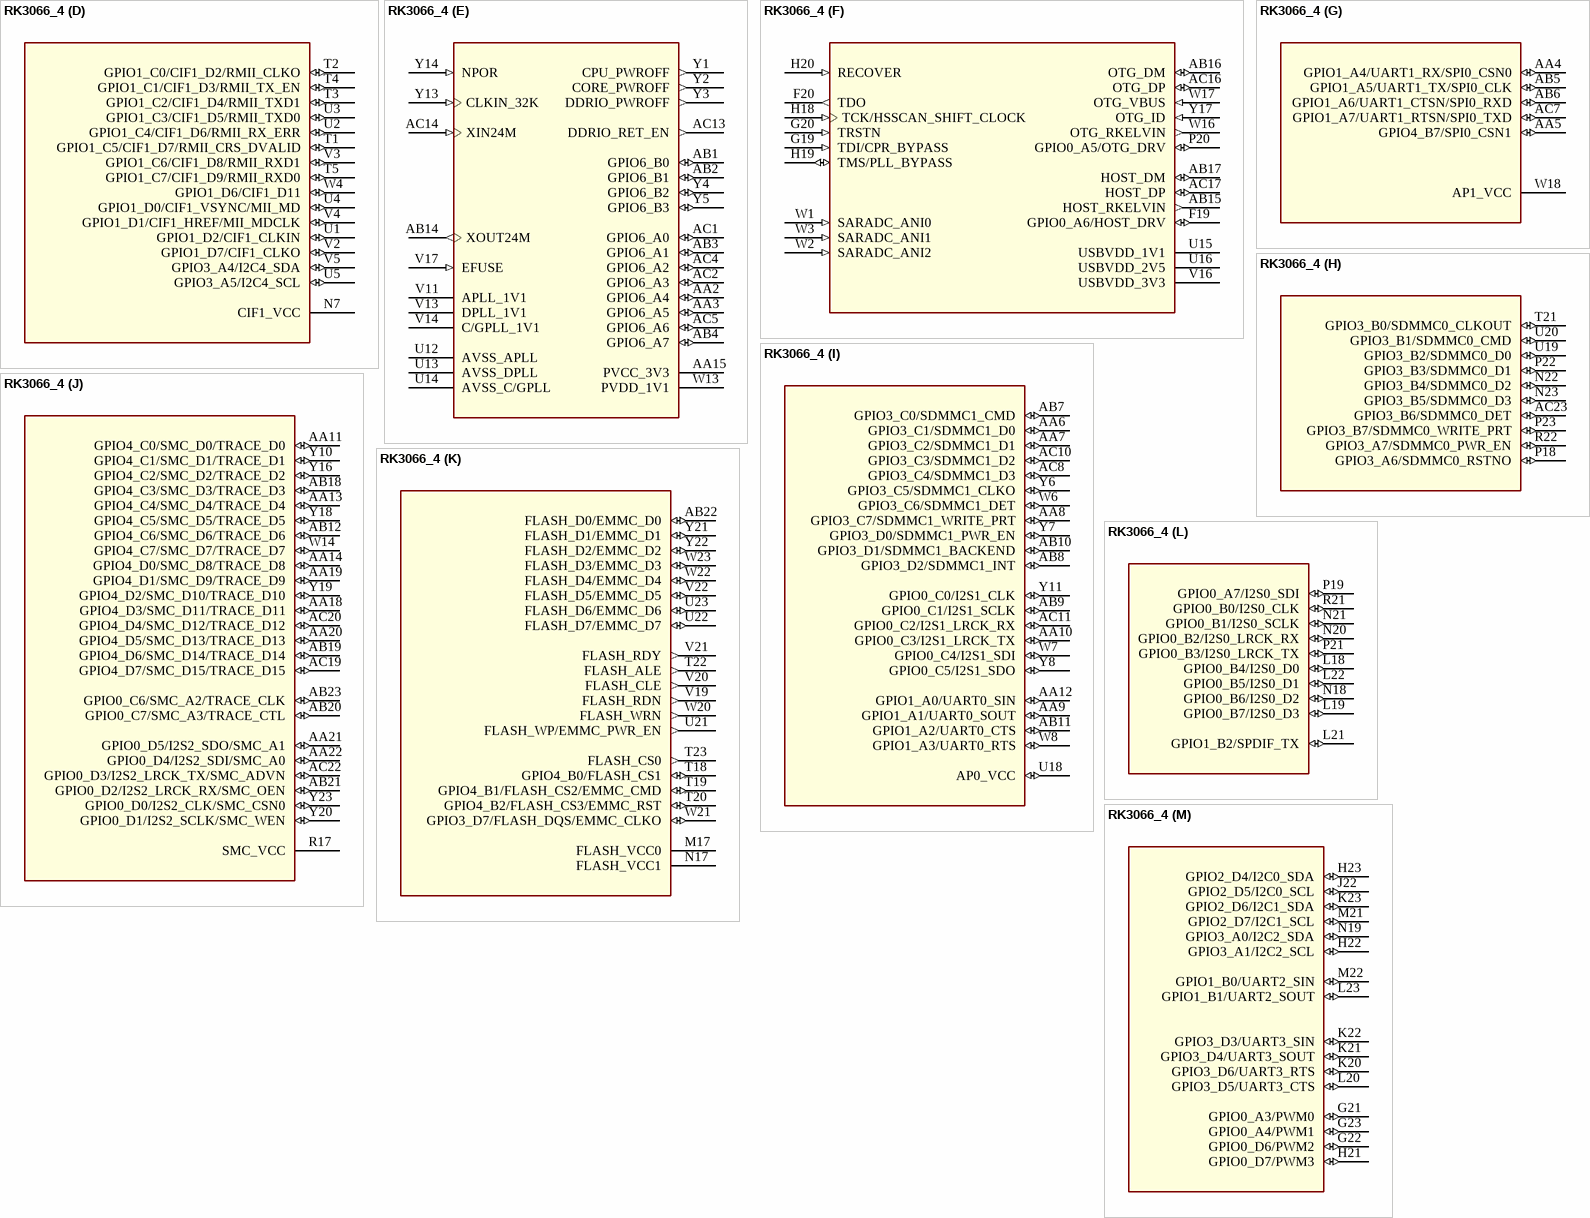
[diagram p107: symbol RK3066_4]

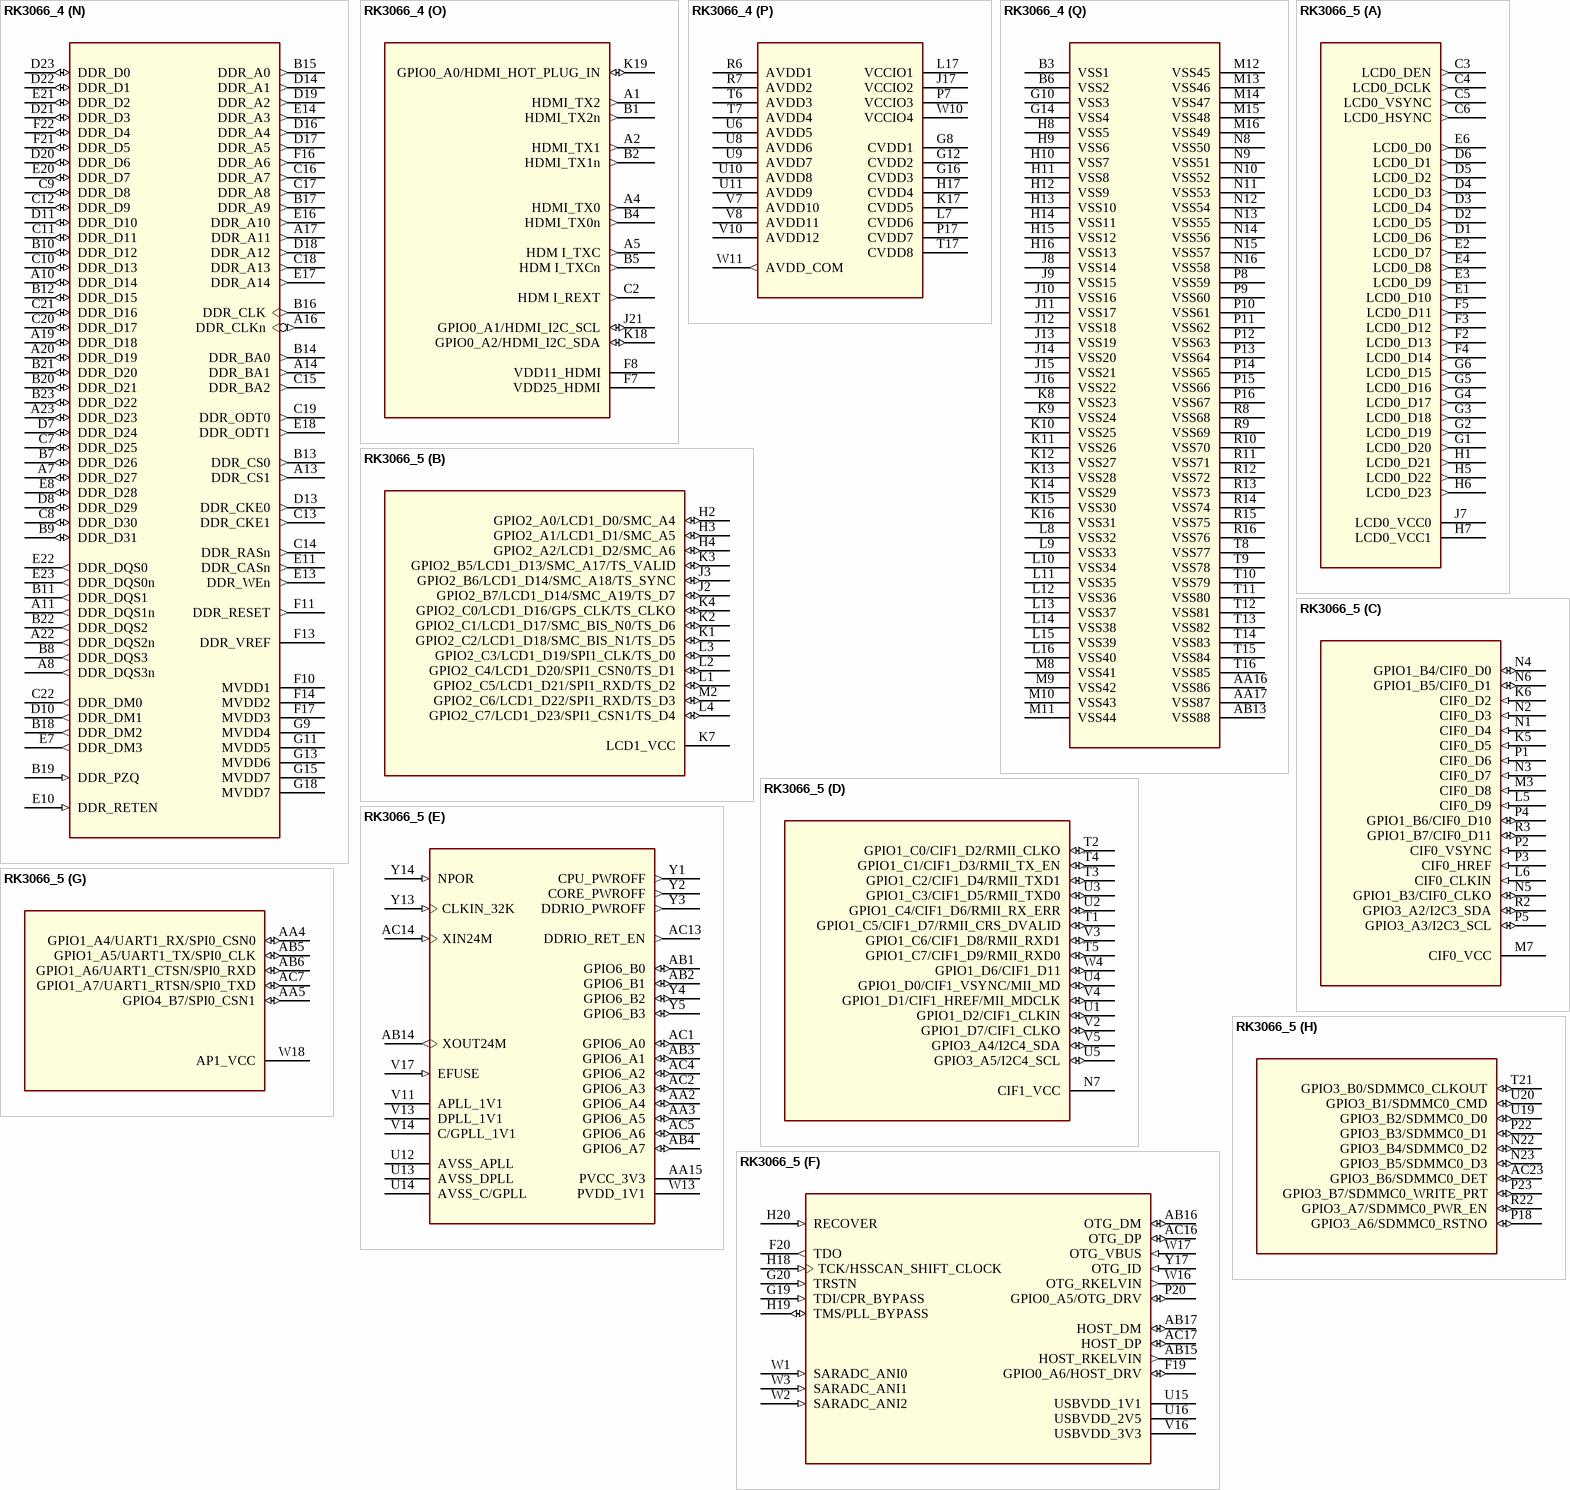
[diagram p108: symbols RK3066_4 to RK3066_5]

## RK3066_4
designator U?
Altium-Right: 150; Altium-Bottom: 250; Altium-Right1: 230; Altium-Bottom1: 180; Altium-Right2: 160; Altium-Bottom2: 120; Altium-Bottom3: 130; Altium-Bottom4: 280; Altium-Bottom5: 310; Altium-Bottom6: 270; Altium-Bottom7: 140; Altium-Bottom9: 530; Altium-Right11: 110; Altium-Bottom11: 170; Altium-Right12: 100; Altium-Bottom12: 470; Altium-Right13: 80; Altium-Bottom13: 350; Altium-Right14: 200; Altium-Bottom14: 190
footprint BGA453
part A pins: C3 LCD0_DEN (out), C4 LCD0_DCLK (out), C5 LCD0_VSYNC (out), C6 LCD0_HSYNC (out), D1 LCD0_D6 (out), D2 LCD0_D5 (out), D3 LCD0_D4 (out), D4 LCD0_D3 (out), D5 LCD0_D2 (out), D6 LCD0_D1 (out), E1 LCD0_D10 (out), E2 LCD0_D7 (out), E3 LCD0_D9 (out), E4 LCD0_D8 (out), E6 LCD0_D0 (out), F2 LCD0_D13 (out), F3 LCD0_D12 (out), F4 LCD0_D14 (out), F5 LCD0_D11 (out), G1 LCD0_D20 (out), G2 LCD0_D19 (out), G3 LCD0_D18 (out), G4 LCD0_D17 (out), G5 LCD0_D16 (out), G6 LCD0_D15 (out), H1 LCD0_D21 (out), H5 LCD0_D22 (out), H6 LCD0_D23 (out), H7 LCD0_VCC1 (power), J7 LCD0_VCC0 (power)
part B pins: H2 GPIO2_A0/LCD1_D0/SMC_A4 (io), H3 GPIO2_A1/LCD1_D1/SMC_A5 (io), H4 GPIO2_A2/LCD1_D2/SMC_A6 (io), J2 GPIO2_B7/LCD1_D14/SMC_A19/TS_D7 (io), J3 GPIO2_B6/LCD1_D14/SMC_A18/TS_SYNC (io), K1 GPIO2_C2/LCD1_D18/SMC_BIS_N1/TS_D5 (io), K2 GPIO2_C1/LCD1_D17/SMC_BIS_N0/TS_D6 (io), K3 GPIO2_B5/LCD1_D13/SMC_A17/TS_VALID (io), K4 GPIO2_C0/LCD1_D16/GPS_CLK/TS_CLKO (io), K7 LCD1_VCC (power), L1 GPIO2_C5/LCD1_D21/SPI1_RXD/TS_D2 (io), L2 GPIO2_C4/LCD1_D20/SPI1_CSN0/TS_D1 (io), L3 GPIO2_C3/LCD1_D19/SPI1_CLK/TS_D0 (io), L4 GPIO2_C7/LCD1_D23/SPI1_CSN1/TS_D4 (io), M2 GPIO2_C6/LCD1_D22/SPI1_RXD/TS_D3 (io)
part C pins: K5 CIF0_D5 (in), K6 CIF0_D2 (in), L5 CIF0_D9 (in), L6 CIF0_CLKIN (in), M3 CIF0_D8 (in), M7 CIF0_VCC (power), N1 CIF0_D4 (in), N2 CIF0_D3 (in), N3 CIF0_D7 (in), N4 GPIO1_B4/CIF0_D0 (io), N5 GPIO1_B3/CIF0_CLKO (io), N6 GPIO1_B5/CIF0_D1 (io), P1 CIF0_D6 (in), P2 CIF0_VSYNC (in), P3 CIF0_HREF (in), P4 GPIO1_B6/CIF0_D10 (io), P5 GPIO3_A3/I2C3_SCL (io), R2 GPIO3_A2/I2C3_SDA (io), R3 GPIO1_B7/CIF0_D11 (io)
part D pins: N7 CIF1_VCC (power), T1 GPIO1_C5/CIF1_D7/RMII_CRS_DVALID (io), T2 GPIO1_C0/CIF1_D2/RMII_CLKO (io), T3 GPIO1_C2/CIF1_D4/RMII_TXD1 (io), T4 GPIO1_C1/CIF1_D3/RMII_TX_EN (io), T5 GPIO1_C7/CIF1_D9/RMII_RXD0 (io), U1 GPIO1_D2/CIF1_CLKIN (io), U2 GPIO1_C4/CIF1_D6/RMII_RX_ERR (io), U3 GPIO1_C3/CIF1_D5/RMII_TXD0 (io), U4 GPIO1_D0/CIF1_VSYNC/MII_MD (io), U5 GPIO3_A5/I2C4_SCL (io), V2 GPIO1_D7/CIF1_CLKO (io), V3 GPIO1_C6/CIF1_D8/RMII_RXD1 (io), V4 GPIO1_D1/CIF1_HREF/MII_MDCLK (io), V5 GPIO3_A4/I2C4_SDA (io), W4 GPIO1_D6/CIF1_D11 (io)
part E pins: AA2 GPIO6_A4 (io), AA3 GPIO6_A5 (io), AA15 PVCC_3V3 (power), AB1 GPIO6_B0 (io), AB2 GPIO6_B1 (io), AB3 GPIO6_A1 (io), AB4 GPIO6_A7 (io), AB14 XOUT24M (out), AC1 GPIO6_A0 (io), AC2 GPIO6_A3 (io), AC4 GPIO6_A2 (io), AC5 GPIO6_A6 (io), AC13 DDRIO_RET_EN (out), AC14 XIN24M (in), U12 AVSS_APLL (power), U13 AVSS_DPLL (power), U14 AVSS_C/GPLL (power), V11 APLL_1V1 (power), V13 DPLL_1V1 (power), V14 C/GPLL_1V1 (power), V17 EFUSE (in), W13 PVDD_1V1 (power), Y1 CPU_PWROFF (out), Y2 CORE_PWROFF (out), Y3 DDRIO_PWROFF (out), Y4 GPIO6_B2 (io), Y5 GPIO6_B3 (io), Y13 CLKIN_32K (in), Y14 NPOR (in)
part F pins: AB15 HOST_RKELVIN (out), AB16 OTG_DM (io), AB17 HOST_DM (io), AC16 OTG_DP (io), AC17 HOST_DP (io), F19 GPIO0_A6/HOST_DRV (io), F20 TDO (out), G19 TDI/CPR_BYPASS (in), G20 TRSTN (in), H18 TCK/HSSCAN_SHIFT_CLOCK (in), H19 TMS/PLL_BYPASS (io), H20 RECOVER (in), P20 GPIO0_A5/OTG_DRV (io), U15 USBVDD_1V1 (power), U16 USBVDD_2V5 (power), V16 USBVDD_3V3 (power), W1 SARADC_ANI0 (in), W2 SARADC_ANI2 (in), W3 SARADC_ANI1 (in), W16 OTG_RKELVIN (out), W17 OTG_VBUS (in), Y17 OTG_ID (in)
part G pins: AA4 GPIO1_A4/UART1_RX/SPI0_CSN0 (io), AA5 GPIO4_B7/SPI0_CSN1 (io), AB5 GPIO1_A5/UART1_TX/SPI0_CLK (io), AB6 GPIO1_A6/UART1_CTSN/SPI0_RXD (io), AC7 GPIO1_A7/UART1_RTSN/SPI0_TXD (io), W18 AP1_VCC (power)
part H pins: AC23 GPIO3_B6/SDMMC0_DET (io), N22 GPIO3_B4/SDMMC0_D2 (io), N23 GPIO3_B5/SDMMC0_D3 (io), P18 GPIO3_A6/SDMMC0_RSTNO (io), P22 GPIO3_B3/SDMMC0_D1 (io), P23 GPIO3_B7/SDMMC0_WRITE_PRT (io), R22 GPIO3_A7/SDMMC0_PWR_EN (io), T21 GPIO3_B0/SDMMC0_CLKOUT (io), U19 GPIO3_B2/SDMMC0_D0 (io), U20 GPIO3_B1/SDMMC0_CMD (io)
part I pins: AA6 GPIO3_C1/SDMMC1_D0 (io), AA7 GPIO3_C2/SDMMC1_D1 (io), AA8 GPIO3_C7/SDMMC1_WRITE_PRT (io), AA9 GPIO1_A1/UART0_SOUT (io), AA10 GPIO0_C3/I2S1_LRCK_TX (io), AA12 GPIO1_A0/UART0_SIN (io), AB7 GPIO3_C0/SDMMC1_CMD (io), AB8 GPIO3_D2/SDMMC1_INT (io), AB9 GPIO0_C1/I2S1_SCLK (io), AB10 GPIO3_D1/SDMMC1_BACKEND (io), AB11 GPIO1_A2/UART0_CTS (io), AC8 GPIO3_C4/SDMMC1_D3 (io), AC10 GPIO3_C3/SDMMC1_D2 (io), AC11 GPIO0_C2/I2S1_LRCK_RX (io), U18 AP0_VCC (io), W6 GPIO3_C6/SDMMC1_DET (io), W7 GPIO0_C4/I2S1_SDI (io), W8 GPIO1_A3/UART0_RTS (io), Y6 GPIO3_C5/SDMMC1_CLKO (io), Y7 GPIO3_D0/SDMMC1_PWR_EN (io), Y8 GPIO0_C5/I2S1_SDO (io), Y11 GPIO0_C0/I2S1_CLK (io)
part J pins: AA11 GPIO4_C0/SMC_D0/TRACE_D0 (io), AA13 GPIO4_C4/SMC_D4/TRACE_D4 (io), AA14 GPIO4_D0/SMC_D8/TRACE_D8 (io), AA18 GPIO4_D3/SMC_D11/TRACE_D11 (io), AA19 GPIO4_D1/SMC_D9/TRACE_D9 (io), AA20 GPIO4_D5/SMC_D13/TRACE_D13 (io), AA21 GPIO0_D5/I2S2_SDO/SMC_A1 (io), AA22 GPIO0_D4/I2S2_SDI/SMC_A0 (io), AB12 GPIO4_C6/SMC_D6/TRACE_D6 (io), AB18 GPIO4_C3/SMC_D3/TRACE_D3 (io), AB19 GPIO4_D6/SMC_D14/TRACE_D14 (io), AB20 GPIO0_C7/SMC_A3/TRACE_CTL (io), AB21 GPIO0_D2/I2S2_LRCK_RX/SMC_OEN (io), AB23 GPIO0_C6/SMC_A2/TRACE_CLK (io), AC19 GPIO4_D7/SMC_D15/TRACE_D15 (io), AC20 GPIO4_D4/SMC_D12/TRACE_D12 (io), AC22 GPIO0_D3/I2S2_LRCK_TX/SMC_ADVN (io), R17 SMC_VCC (power), W14 GPIO4_C7/SMC_D7/TRACE_D7 (io), Y10 GPIO4_C1/SMC_D1/TRACE_D1 (io), Y16 GPIO4_C2/SMC_D2/TRACE_D2 (io), Y18 GPIO4_C5/SMC_D5/TRACE_D5 (io), Y19 GPIO4_D2/SMC_D10/TRACE_D10 (io), Y20 GPIO0_D1/I2S2_SCLK/SMC_WEN (io), Y23 GPIO0_D0/I2S2_CLK/SMC_CSN0 (io)
part K pins: AB22 FLASH_D0/EMMC_D0 (io), M17 FLASH_VCC0 (power), N17 FLASH_VCC1 (power), T18 GPIO4_B0/FLASH_CS1 (io), T19 GPIO4_B1/FLASH_CS2/EMMC_CMD (io), T20 GPIO4_B2/FLASH_CS3/EMMC_RST (io), T22 FLASH_ALE (out), T23 FLASH_CS0 (out), U21 FLASH_WP/EMMC_PWR_EN (out), U22 FLASH_D7/EMMC_D7 (io), U23 FLASH_D6/EMMC_D6 (io), V19 FLASH_RDN (out), V20 FLASH_CLE (out), V21 FLASH_RDY (out), V22 FLASH_D5/EMMC_D5 (io), W20 FLASH_WRN (out), W21 GPIO3_D7/FLASH_DQS/EMMC_CLKO (io), W22 FLASH_D4/EMMC_D4 (io), W23 FLASH_D3/EMMC_D3 (io), Y21 FLASH_D1/EMMC_D1 (io), Y22 FLASH_D2/EMMC_D2 (io)
part L pins: L18 GPIO0_B4/I2S0_D0 (io), L19 GPIO0_B7/I2S0_D3 (io), L21 GPIO1_B2/SPDIF_TX (io), L22 GPIO0_B5/I2S0_D1 (io), N18 GPIO0_B6/I2S0_D2 (io), N20 GPIO0_B2/I2S0_LRCK_RX (io), N21 GPIO0_B1/I2S0_SCLK (io), P19 GPIO0_A7/I2S0_SDI (io), P21 GPIO0_B3/I2S0_LRCK_TX (io), R21 GPIO0_B0/I2S0_CLK (io)
part M pins: G21 GPIO0_A3/PWM0 (io), G22 GPIO0_D6/PWM2 (io), G23 GPIO0_A4/PWM1 (io), H21 GPIO0_D7/PWM3 (io), H22 GPIO3_A1/I2C2_SCL (io), H23 GPIO2_D4/I2C0_SDA (io), J22 GPIO2_D5/I2C0_SCL (io), K20 GPIO3_D6/UART3_RTS (io), K21 GPIO3_D4/UART3_SOUT (io), K22 GPIO3_D3/UART3_SIN (io), K23 GPIO2_D6/I2C1_SDA (io), L20 GPIO3_D5/UART3_CTS (io), L23 GPIO1_B1/UART2_SOUT (io), M21 GPIO2_D7/I2C1_SCL (io), M22 GPIO1_B0/UART2_SIN (io), N19 GPIO3_A0/I2C2_SDA (io)
part N pins: A7 DDR_D27 (io), A8 DDR_DQS3n (out), A10 DDR_D14 (io), A11 DDR_DQS1n (out), A13 DDR_CS1 (out), A14 DDR_BA1 (out), A16 DDR_CLKn (out), A17 DDR_A11 (out), A19 DDR_D18 (io), A20 DDR_D19 (io), A22 DDR_DQS2n (out), A23 DDR_D23 (io), B7 DDR_D26 (io), B8 DDR_DQS3 (out), B9 DDR_D31 (io), B10 DDR_D12 (io), B11 DDR_DQS1 (out), B12 DDR_D15 (io), B13 DDR_CS0 (out), B14 DDR_BA0 (out), B15 DDR_A0 (out), B16 DDR_CLK (out), B17 DDR_A9 (out), B18 DDR_DM2 (out), B19 DDR_PZQ (in), B20 DDR_D21 (io), B21 DDR_D20 (io), B22 DDR_DQS2 (out), B23 DDR_D22 (io), C7 DDR_D25 (io), C8 DDR_D30 (io), C9 DDR_D8 (io), C10 DDR_D13 (io), C11 DDR_D11 (io), C12 DDR_D9 (io), C13 DDR_CKE1 (out), C14 DDR_RASn (out), C15 DDR_BA2 (out), C16 DDR_A7 (out), C17 DDR_A8 (out), C18 DDR_A13 (out), C19 DDR_ODT0 (out), C20 DDR_D17 (io), C21 DDR_D16 (io), C22 DDR_DM0 (out), D7 DDR_D24 (io), D8 DDR_D29 (io), D10 DDR_DM1 (out), D11 DDR_D10 (io), D13 DDR_CKE0 (out), D14 DDR_A1 (out), D16 DDR_A4 (out), D17 DDR_A5 (out), D18 DDR_A12 (out), D19 DDR_A2 (out), D20 DDR_D6 (io), D21 DDR_D3 (io), D22 DDR_D1 (io), D23 DDR_D0 (io), E7 DDR_DM3 (out), E8 DDR_D28 (io), E10 DDR_RETEN (in), E11 DDR_CASn (out), E13 DDR_WEn (out), E14 DDR_A3 (out), E16 DDR_A10 (out), E17 DDR_A14 (out), E18 DDR_ODT1 (out), E20 DDR_D7 (io), E21 DDR_D2 (io), E22 DDR_DQS0 (out), E23 DDR_DQS0n (out), F10 MVDD1 (power), F11 DDR_RESET (out), F13 DDR_VREF (power), F14 MVDD2 (power), F16 DDR_A6 (out), F17 MVDD3 (power), F21 DDR_D5 (io), F22 DDR_D4 (io), G9 MVDD4 (power), G11 MVDD5 (power), G13 MVDD6 (power), G15 MVDD7 (power), G18 MVDD7 (power)
part O pins: A1 HDMI_TX2 (out), A2 HDMI_TX1 (out), A4 HDMI_TX0 (out), A5 HDM I_TXC (out), B1 HDMI_TX2n (out), B2 HDMI_TX1n (out), B4 HDMI_TX0n (out), B5 HDM I_TXCn (out), C2 HDM I_REXT (out), F7 VDD25_HDMI (power), F8 VDD11_HDMI (power), J21 GPIO0_A1/HDMI_I2C_SCL (io), K18 GPIO0_A2/HDMI_I2C_SDA (io), K19 GPIO0_A0/HDMI_HOT_PLUG_IN (io)
part P pins: G8 CVDD1 (power), G12 CVDD2 (power), G16 CVDD3 (power), H17 CVDD4 (power), J17 VCCIO2 (power), K17 CVDD5 (power), L7 CVDD6 (power), L17 VCCIO1 (power), P7 VCCIO3 (power), P17 CVDD7 (power), R6 AVDD1 (power), R7 AVDD2 (power), T6 AVDD3 (power), T7 AVDD4 (power), T17 CVDD8 (power), U6 AVDD5 (power), U8 AVDD6 (power), U9 AVDD7 (power), U10 AVDD8 (power), U11 AVDD9 (power), V7 AVDD10 (power), V8 AVDD11 (power), V10 AVDD12 (power), W10 VCCIO4 (power), W11 AVDD_COM (out)
part Q pins: AA16 VSS86 (power), AA17 VSS87 (power), AB13 VSS88 (power), B3 VSS1 (power), B6 VSS2 (power), G10 VSS3 (power), G14 VSS4 (power), H8 VSS5 (power), H9 VSS6 (power), H10 VSS7 (power), H11 VSS8 (power), H12 VSS9 (power), H13 VSS10 (power), H14 VSS11 (power), H15 VSS12 (power), H16 VSS13 (power), J8 VSS14 (power), J9 VSS15 (power), J10 VSS16 (power), J11 VSS17 (power), J12 VSS18 (power), J13 VSS19 (power), J14 VSS20 (power), J15 VSS21 (power), J16 VSS22 (power), K8 VSS23 (power), K9 VSS24 (power), K10 VSS25 (power), K11 VSS26 (power), K12 VSS27 (power), K13 VSS28 (power), K14 VSS29 (power), K15 VSS30 (power), K16 VSS31 (power), L8 VSS32 (power), L9 VSS33 (power), L10 VSS34 (power), L11 VSS35 (power), L12 VSS36 (power), L13 VSS37 (power), L14 VSS38 (power), L15 VSS39 (power), L16 VSS40 (power), M8 VSS41 (power), M9 VSS42 (power), M10 VSS43 (power), M11 VSS44 (power), M12 VSS45 (power), M13 VSS46 (power), M14 VSS47 (power), M15 VSS48 (power), M16 VSS49 (power), N8 VSS50 (power), N9 VSS51 (power), N10 VSS52 (power), N11 VSS53 (power), N12 VSS54 (power), N13 VSS55 (power), N14 VSS56 (power), N15 VSS57 (power), N16 VSS58 (power), P8 VSS59 (power), P9 VSS60 (power), P10 VSS61 (power), P11 VSS62 (power), P12 VSS63 (power), P13 VSS64 (power), P14 VSS65 (power), P15 VSS66 (power), P16 VSS67 (power), R8 VSS68 (power), R9 VSS69 (power), R10 VSS70 (power), R11 VSS71 (power), R12 VSS72 (power), R13 VSS73 (power), R14 VSS74 (power), R15 VSS75 (power), R16 VSS76 (power), T8 VSS77 (power), T9 VSS78 (power), T10 VSS79 (power), T11 VSS80 (power), T12 VSS81 (power), T13 VSS82 (power), T14 VSS83 (power), T15 VSS84 (power), T16 VSS85 (power)

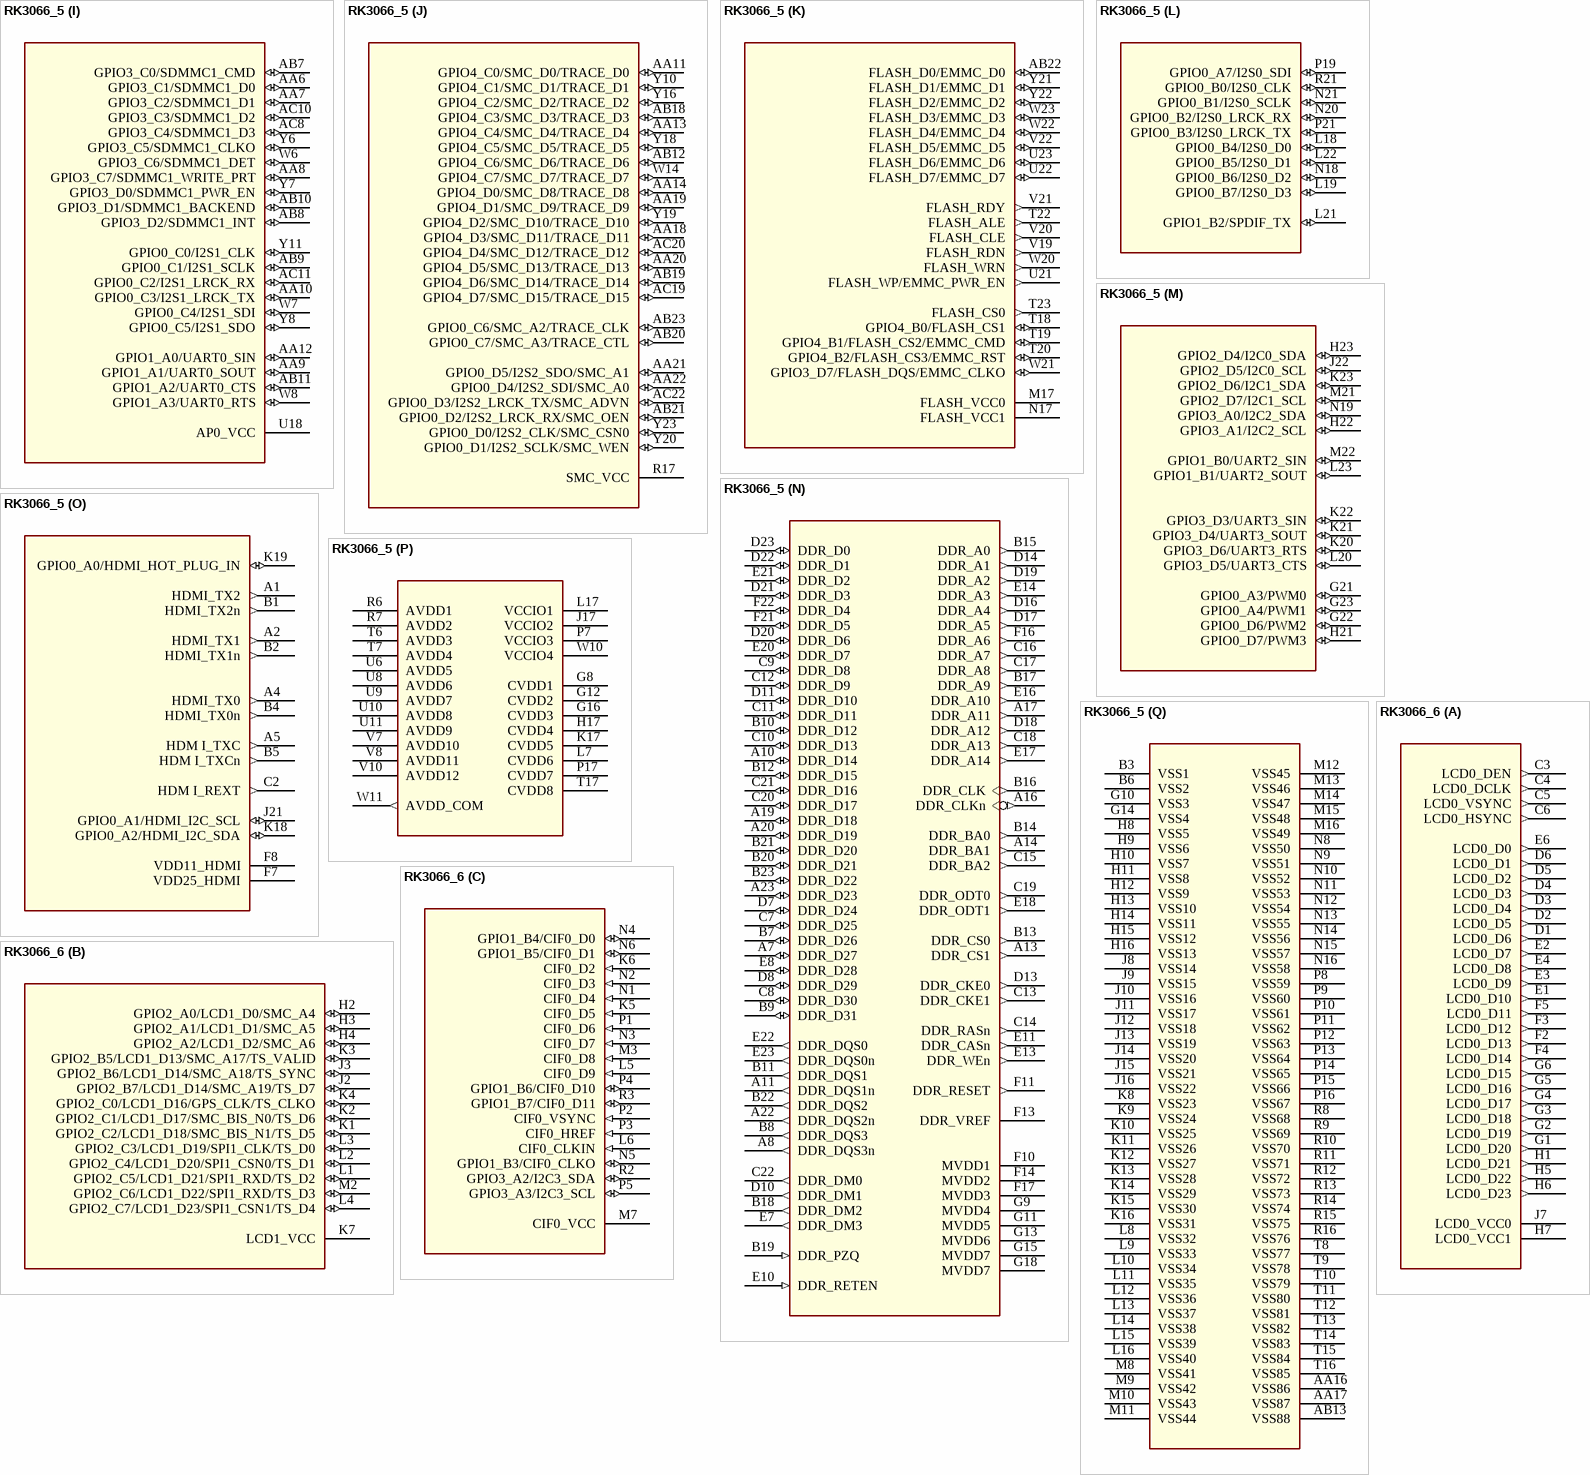
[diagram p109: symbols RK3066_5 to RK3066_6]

## RK3066_5
designator U?
Altium-Right: 230; Altium-Bottom: 180; Altium-Right1: 160; Altium-Bottom1: 120; Altium-Bottom2: 130; Altium-Bottom3: 280; Altium-Bottom4: 310; Altium-Bottom5: 270; Altium-Bottom6: 140; Altium-Bottom8: 530; Altium-Right9: 150; Altium-Bottom9: 250; Altium-Right10: 110; Altium-Bottom10: 170; Altium-Right11: 100; Altium-Bottom11: 470; Altium-Right12: 80; Altium-Bottom12: 350; Altium-Right13: 200; Altium-Bottom13: 190
footprint BGA453
part A pins: C3 LCD0_DEN (out), C4 LCD0_DCLK (out), C5 LCD0_VSYNC (out), C6 LCD0_HSYNC (out), D1 LCD0_D6 (out), D2 LCD0_D5 (out), D3 LCD0_D4 (out), D4 LCD0_D3 (out), D5 LCD0_D2 (out), D6 LCD0_D1 (out), E1 LCD0_D10 (out), E2 LCD0_D7 (out), E3 LCD0_D9 (out), E4 LCD0_D8 (out), E6 LCD0_D0 (out), F2 LCD0_D13 (out), F3 LCD0_D12 (out), F4 LCD0_D14 (out), F5 LCD0_D11 (out), G1 LCD0_D20 (out), G2 LCD0_D19 (out), G3 LCD0_D18 (out), G4 LCD0_D17 (out), G5 LCD0_D16 (out), G6 LCD0_D15 (out), H1 LCD0_D21 (out), H5 LCD0_D22 (out), H6 LCD0_D23 (out), H7 LCD0_VCC1 (power), J7 LCD0_VCC0 (power)
part B pins: H2 GPIO2_A0/LCD1_D0/SMC_A4 (io), H3 GPIO2_A1/LCD1_D1/SMC_A5 (io), H4 GPIO2_A2/LCD1_D2/SMC_A6 (io), J2 GPIO2_B7/LCD1_D14/SMC_A19/TS_D7 (io), J3 GPIO2_B6/LCD1_D14/SMC_A18/TS_SYNC (io), K1 GPIO2_C2/LCD1_D18/SMC_BIS_N1/TS_D5 (io), K2 GPIO2_C1/LCD1_D17/SMC_BIS_N0/TS_D6 (io), K3 GPIO2_B5/LCD1_D13/SMC_A17/TS_VALID (io), K4 GPIO2_C0/LCD1_D16/GPS_CLK/TS_CLKO (io), K7 LCD1_VCC (power), L1 GPIO2_C5/LCD1_D21/SPI1_RXD/TS_D2 (io), L2 GPIO2_C4/LCD1_D20/SPI1_CSN0/TS_D1 (io), L3 GPIO2_C3/LCD1_D19/SPI1_CLK/TS_D0 (io), L4 GPIO2_C7/LCD1_D23/SPI1_CSN1/TS_D4 (io), M2 GPIO2_C6/LCD1_D22/SPI1_RXD/TS_D3 (io)
part C pins: K5 CIF0_D5 (in), K6 CIF0_D2 (in), L5 CIF0_D9 (in), L6 CIF0_CLKIN (in), M3 CIF0_D8 (in), M7 CIF0_VCC (power), N1 CIF0_D4 (in), N2 CIF0_D3 (in), N3 CIF0_D7 (in), N4 GPIO1_B4/CIF0_D0 (io), N5 GPIO1_B3/CIF0_CLKO (io), N6 GPIO1_B5/CIF0_D1 (io), P1 CIF0_D6 (in), P2 CIF0_VSYNC (in), P3 CIF0_HREF (in), P4 GPIO1_B6/CIF0_D10 (io), P5 GPIO3_A3/I2C3_SCL (io), R2 GPIO3_A2/I2C3_SDA (io), R3 GPIO1_B7/CIF0_D11 (io)
part D pins: N7 CIF1_VCC (power), T1 GPIO1_C5/CIF1_D7/RMII_CRS_DVALID (io), T2 GPIO1_C0/CIF1_D2/RMII_CLKO (io), T3 GPIO1_C2/CIF1_D4/RMII_TXD1 (io), T4 GPIO1_C1/CIF1_D3/RMII_TX_EN (io), T5 GPIO1_C7/CIF1_D9/RMII_RXD0 (io), U1 GPIO1_D2/CIF1_CLKIN (io), U2 GPIO1_C4/CIF1_D6/RMII_RX_ERR (io), U3 GPIO1_C3/CIF1_D5/RMII_TXD0 (io), U4 GPIO1_D0/CIF1_VSYNC/MII_MD (io), U5 GPIO3_A5/I2C4_SCL (io), V2 GPIO1_D7/CIF1_CLKO (io), V3 GPIO1_C6/CIF1_D8/RMII_RXD1 (io), V4 GPIO1_D1/CIF1_HREF/MII_MDCLK (io), V5 GPIO3_A4/I2C4_SDA (io), W4 GPIO1_D6/CIF1_D11 (io)
part E pins: AA2 GPIO6_A4 (io), AA3 GPIO6_A5 (io), AA15 PVCC_3V3 (power), AB1 GPIO6_B0 (io), AB2 GPIO6_B1 (io), AB3 GPIO6_A1 (io), AB4 GPIO6_A7 (io), AB14 XOUT24M (out), AC1 GPIO6_A0 (io), AC2 GPIO6_A3 (io), AC4 GPIO6_A2 (io), AC5 GPIO6_A6 (io), AC13 DDRIO_RET_EN (out), AC14 XIN24M (in), U12 AVSS_APLL (power), U13 AVSS_DPLL (power), U14 AVSS_C/GPLL (power), V11 APLL_1V1 (power), V13 DPLL_1V1 (power), V14 C/GPLL_1V1 (power), V17 EFUSE (in), W13 PVDD_1V1 (power), Y1 CPU_PWROFF (out), Y2 CORE_PWROFF (out), Y3 DDRIO_PWROFF (out), Y4 GPIO6_B2 (io), Y5 GPIO6_B3 (io), Y13 CLKIN_32K (in), Y14 NPOR (in)
part F pins: AB15 HOST_RKELVIN (out), AB16 OTG_DM (io), AB17 HOST_DM (io), AC16 OTG_DP (io), AC17 HOST_DP (io), F19 GPIO0_A6/HOST_DRV (io), F20 TDO (out), G19 TDI/CPR_BYPASS (in), G20 TRSTN (in), H18 TCK/HSSCAN_SHIFT_CLOCK (in), H19 TMS/PLL_BYPASS (io), H20 RECOVER (in), P20 GPIO0_A5/OTG_DRV (io), U15 USBVDD_1V1 (power), U16 USBVDD_2V5 (power), V16 USBVDD_3V3 (power), W1 SARADC_ANI0 (in), W2 SARADC_ANI2 (in), W3 SARADC_ANI1 (in), W16 OTG_RKELVIN (out), W17 OTG_VBUS (in), Y17 OTG_ID (in)
part G pins: AA4 GPIO1_A4/UART1_RX/SPI0_CSN0 (io), AA5 GPIO4_B7/SPI0_CSN1 (io), AB5 GPIO1_A5/UART1_TX/SPI0_CLK (io), AB6 GPIO1_A6/UART1_CTSN/SPI0_RXD (io), AC7 GPIO1_A7/UART1_RTSN/SPI0_TXD (io), W18 AP1_VCC (power)
part H pins: AC23 GPIO3_B6/SDMMC0_DET (io), N22 GPIO3_B4/SDMMC0_D2 (io), N23 GPIO3_B5/SDMMC0_D3 (io), P18 GPIO3_A6/SDMMC0_RSTNO (io), P22 GPIO3_B3/SDMMC0_D1 (io), P23 GPIO3_B7/SDMMC0_WRITE_PRT (io), R22 GPIO3_A7/SDMMC0_PWR_EN (io), T21 GPIO3_B0/SDMMC0_CLKOUT (io), U19 GPIO3_B2/SDMMC0_D0 (io), U20 GPIO3_B1/SDMMC0_CMD (io)
part I pins: AA6 GPIO3_C1/SDMMC1_D0 (io), AA7 GPIO3_C2/SDMMC1_D1 (io), AA8 GPIO3_C7/SDMMC1_WRITE_PRT (io), AA9 GPIO1_A1/UART0_SOUT (io), AA10 GPIO0_C3/I2S1_LRCK_TX (io), AA12 GPIO1_A0/UART0_SIN (io), AB7 GPIO3_C0/SDMMC1_CMD (io), AB8 GPIO3_D2/SDMMC1_INT (io), AB9 GPIO0_C1/I2S1_SCLK (io), AB10 GPIO3_D1/SDMMC1_BACKEND (io), AB11 GPIO1_A2/UART0_CTS (io), AC8 GPIO3_C4/SDMMC1_D3 (io), AC10 GPIO3_C3/SDMMC1_D2 (io), AC11 GPIO0_C2/I2S1_LRCK_RX (io), U18 AP0_VCC (power), W6 GPIO3_C6/SDMMC1_DET (io), W7 GPIO0_C4/I2S1_SDI (io), W8 GPIO1_A3/UART0_RTS (io), Y6 GPIO3_C5/SDMMC1_CLKO (io), Y7 GPIO3_D0/SDMMC1_PWR_EN (io), Y8 GPIO0_C5/I2S1_SDO (io), Y11 GPIO0_C0/I2S1_CLK (io)
part J pins: AA11 GPIO4_C0/SMC_D0/TRACE_D0 (io), AA13 GPIO4_C4/SMC_D4/TRACE_D4 (io), AA14 GPIO4_D0/SMC_D8/TRACE_D8 (io), AA18 GPIO4_D3/SMC_D11/TRACE_D11 (io), AA19 GPIO4_D1/SMC_D9/TRACE_D9 (io), AA20 GPIO4_D5/SMC_D13/TRACE_D13 (io), AA21 GPIO0_D5/I2S2_SDO/SMC_A1 (io), AA22 GPIO0_D4/I2S2_SDI/SMC_A0 (io), AB12 GPIO4_C6/SMC_D6/TRACE_D6 (io), AB18 GPIO4_C3/SMC_D3/TRACE_D3 (io), AB19 GPIO4_D6/SMC_D14/TRACE_D14 (io), AB20 GPIO0_C7/SMC_A3/TRACE_CTL (io), AB21 GPIO0_D2/I2S2_LRCK_RX/SMC_OEN (io), AB23 GPIO0_C6/SMC_A2/TRACE_CLK (io), AC19 GPIO4_D7/SMC_D15/TRACE_D15 (io), AC20 GPIO4_D4/SMC_D12/TRACE_D12 (io), AC22 GPIO0_D3/I2S2_LRCK_TX/SMC_ADVN (io), R17 SMC_VCC (power), W14 GPIO4_C7/SMC_D7/TRACE_D7 (io), Y10 GPIO4_C1/SMC_D1/TRACE_D1 (io), Y16 GPIO4_C2/SMC_D2/TRACE_D2 (io), Y18 GPIO4_C5/SMC_D5/TRACE_D5 (io), Y19 GPIO4_D2/SMC_D10/TRACE_D10 (io), Y20 GPIO0_D1/I2S2_SCLK/SMC_WEN (io), Y23 GPIO0_D0/I2S2_CLK/SMC_CSN0 (io)
part K pins: AB22 FLASH_D0/EMMC_D0 (io), M17 FLASH_VCC0 (power), N17 FLASH_VCC1 (power), T18 GPIO4_B0/FLASH_CS1 (io), T19 GPIO4_B1/FLASH_CS2/EMMC_CMD (io), T20 GPIO4_B2/FLASH_CS3/EMMC_RST (io), T22 FLASH_ALE (out), T23 FLASH_CS0 (out), U21 FLASH_WP/EMMC_PWR_EN (out), U22 FLASH_D7/EMMC_D7 (io), U23 FLASH_D6/EMMC_D6 (io), V19 FLASH_RDN (out), V20 FLASH_CLE (out), V21 FLASH_RDY (out), V22 FLASH_D5/EMMC_D5 (io), W20 FLASH_WRN (out), W21 GPIO3_D7/FLASH_DQS/EMMC_CLKO (io), W22 FLASH_D4/EMMC_D4 (io), W23 FLASH_D3/EMMC_D3 (io), Y21 FLASH_D1/EMMC_D1 (io), Y22 FLASH_D2/EMMC_D2 (io)
part L pins: L18 GPIO0_B4/I2S0_D0 (io), L19 GPIO0_B7/I2S0_D3 (io), L21 GPIO1_B2/SPDIF_TX (io), L22 GPIO0_B5/I2S0_D1 (io), N18 GPIO0_B6/I2S0_D2 (io), N20 GPIO0_B2/I2S0_LRCK_RX (io), N21 GPIO0_B1/I2S0_SCLK (io), P19 GPIO0_A7/I2S0_SDI (io), P21 GPIO0_B3/I2S0_LRCK_TX (io), R21 GPIO0_B0/I2S0_CLK (io)
part M pins: G21 GPIO0_A3/PWM0 (io), G22 GPIO0_D6/PWM2 (io), G23 GPIO0_A4/PWM1 (io), H21 GPIO0_D7/PWM3 (io), H22 GPIO3_A1/I2C2_SCL (io), H23 GPIO2_D4/I2C0_SDA (io), J22 GPIO2_D5/I2C0_SCL (io), K20 GPIO3_D6/UART3_RTS (io), K21 GPIO3_D4/UART3_SOUT (io), K22 GPIO3_D3/UART3_SIN (io), K23 GPIO2_D6/I2C1_SDA (io), L20 GPIO3_D5/UART3_CTS (io), L23 GPIO1_B1/UART2_SOUT (io), M21 GPIO2_D7/I2C1_SCL (io), M22 GPIO1_B0/UART2_SIN (io), N19 GPIO3_A0/I2C2_SDA (io)
part N pins: A7 DDR_D27 (io), A8 DDR_DQS3n (out), A10 DDR_D14 (io), A11 DDR_DQS1n (out), A13 DDR_CS1 (out), A14 DDR_BA1 (out), A16 DDR_CLKn (out), A17 DDR_A11 (out), A19 DDR_D18 (io), A20 DDR_D19 (io), A22 DDR_DQS2n (out), A23 DDR_D23 (io), B7 DDR_D26 (io), B8 DDR_DQS3 (out), B9 DDR_D31 (io), B10 DDR_D12 (io), B11 DDR_DQS1 (out), B12 DDR_D15 (io), B13 DDR_CS0 (out), B14 DDR_BA0 (out), B15 DDR_A0 (out), B16 DDR_CLK (out), B17 DDR_A9 (out), B18 DDR_DM2 (out), B19 DDR_PZQ (in), B20 DDR_D21 (io), B21 DDR_D20 (io), B22 DDR_DQS2 (out), B23 DDR_D22 (io), C7 DDR_D25 (io), C8 DDR_D30 (io), C9 DDR_D8 (io), C10 DDR_D13 (io), C11 DDR_D11 (io), C12 DDR_D9 (io), C13 DDR_CKE1 (out), C14 DDR_RASn (out), C15 DDR_BA2 (out), C16 DDR_A7 (out), C17 DDR_A8 (out), C18 DDR_A13 (out), C19 DDR_ODT0 (out), C20 DDR_D17 (io), C21 DDR_D16 (io), C22 DDR_DM0 (out), D7 DDR_D24 (io), D8 DDR_D29 (io), D10 DDR_DM1 (out), D11 DDR_D10 (io), D13 DDR_CKE0 (out), D14 DDR_A1 (out), D16 DDR_A4 (out), D17 DDR_A5 (out), D18 DDR_A12 (out), D19 DDR_A2 (out), D20 DDR_D6 (io), D21 DDR_D3 (io), D22 DDR_D1 (io), D23 DDR_D0 (io), E7 DDR_DM3 (out), E8 DDR_D28 (io), E10 DDR_RETEN (in), E11 DDR_CASn (out), E13 DDR_WEn (out), E14 DDR_A3 (out), E16 DDR_A10 (out), E17 DDR_A14 (out), E18 DDR_ODT1 (out), E20 DDR_D7 (io), E21 DDR_D2 (io), E22 DDR_DQS0 (out), E23 DDR_DQS0n (out), F10 MVDD1 (power), F11 DDR_RESET (out), F13 DDR_VREF (power), F14 MVDD2 (power), F16 DDR_A6 (out), F17 MVDD3 (power), F21 DDR_D5 (io), F22 DDR_D4 (io), G9 MVDD4 (power), G11 MVDD5 (power), G13 MVDD6 (power), G15 MVDD7 (power), G18 MVDD7 (power)
part O pins: A1 HDMI_TX2 (out), A2 HDMI_TX1 (out), A4 HDMI_TX0 (out), A5 HDM I_TXC (out), B1 HDMI_TX2n (out), B2 HDMI_TX1n (out), B4 HDMI_TX0n (out), B5 HDM I_TXCn (out), C2 HDM I_REXT (out), F7 VDD25_HDMI (power), F8 VDD11_HDMI (power), J21 GPIO0_A1/HDMI_I2C_SCL (io), K18 GPIO0_A2/HDMI_I2C_SDA (io), K19 GPIO0_A0/HDMI_HOT_PLUG_IN (io)
part P pins: G8 CVDD1 (power), G12 CVDD2 (power), G16 CVDD3 (power), H17 CVDD4 (power), J17 VCCIO2 (power), K17 CVDD5 (power), L7 CVDD6 (power), L17 VCCIO1 (power), P7 VCCIO3 (power), P17 CVDD7 (power), R6 AVDD1 (power), R7 AVDD2 (power), T6 AVDD3 (power), T7 AVDD4 (power), T17 CVDD8 (power), U6 AVDD5 (power), U8 AVDD6 (power), U9 AVDD7 (power), U10 AVDD8 (power), U11 AVDD9 (power), V7 AVDD10 (power), V8 AVDD11 (power), V10 AVDD12 (power), W10 VCCIO4 (power), W11 AVDD_COM (out)
part Q pins: AA16 VSS86 (power), AA17 VSS87 (power), AB13 VSS88 (power), B3 VSS1 (power), B6 VSS2 (power), G10 VSS3 (power), G14 VSS4 (power), H8 VSS5 (power), H9 VSS6 (power), H10 VSS7 (power), H11 VSS8 (power), H12 VSS9 (power), H13 VSS10 (power), H14 VSS11 (power), H15 VSS12 (power), H16 VSS13 (power), J8 VSS14 (power), J9 VSS15 (power), J10 VSS16 (power), J11 VSS17 (power), J12 VSS18 (power), J13 VSS19 (power), J14 VSS20 (power), J15 VSS21 (power), J16 VSS22 (power), K8 VSS23 (power), K9 VSS24 (power), K10 VSS25 (power), K11 VSS26 (power), K12 VSS27 (power), K13 VSS28 (power), K14 VSS29 (power), K15 VSS30 (power), K16 VSS31 (power), L8 VSS32 (power), L9 VSS33 (power), L10 VSS34 (power), L11 VSS35 (power), L12 VSS36 (power), L13 VSS37 (power), L14 VSS38 (power), L15 VSS39 (power), L16 VSS40 (power), M8 VSS41 (power), M9 VSS42 (power), M10 VSS43 (power), M11 VSS44 (power), M12 VSS45 (power), M13 VSS46 (power), M14 VSS47 (power), M15 VSS48 (power), M16 VSS49 (power), N8 VSS50 (power), N9 VSS51 (power), N10 VSS52 (power), N11 VSS53 (power), N12 VSS54 (power), N13 VSS55 (power), N14 VSS56 (power), N15 VSS57 (power), N16 VSS58 (power), P8 VSS59 (power), P9 VSS60 (power), P10 VSS61 (power), P11 VSS62 (power), P12 VSS63 (power), P13 VSS64 (power), P14 VSS65 (power), P15 VSS66 (power), P16 VSS67 (power), R8 VSS68 (power), R9 VSS69 (power), R10 VSS70 (power), R11 VSS71 (power), R12 VSS72 (power), R13 VSS73 (power), R14 VSS74 (power), R15 VSS75 (power), R16 VSS76 (power), T8 VSS77 (power), T9 VSS78 (power), T10 VSS79 (power), T11 VSS80 (power), T12 VSS81 (power), T13 VSS82 (power), T14 VSS83 (power), T15 VSS84 (power), T16 VSS85 (power)

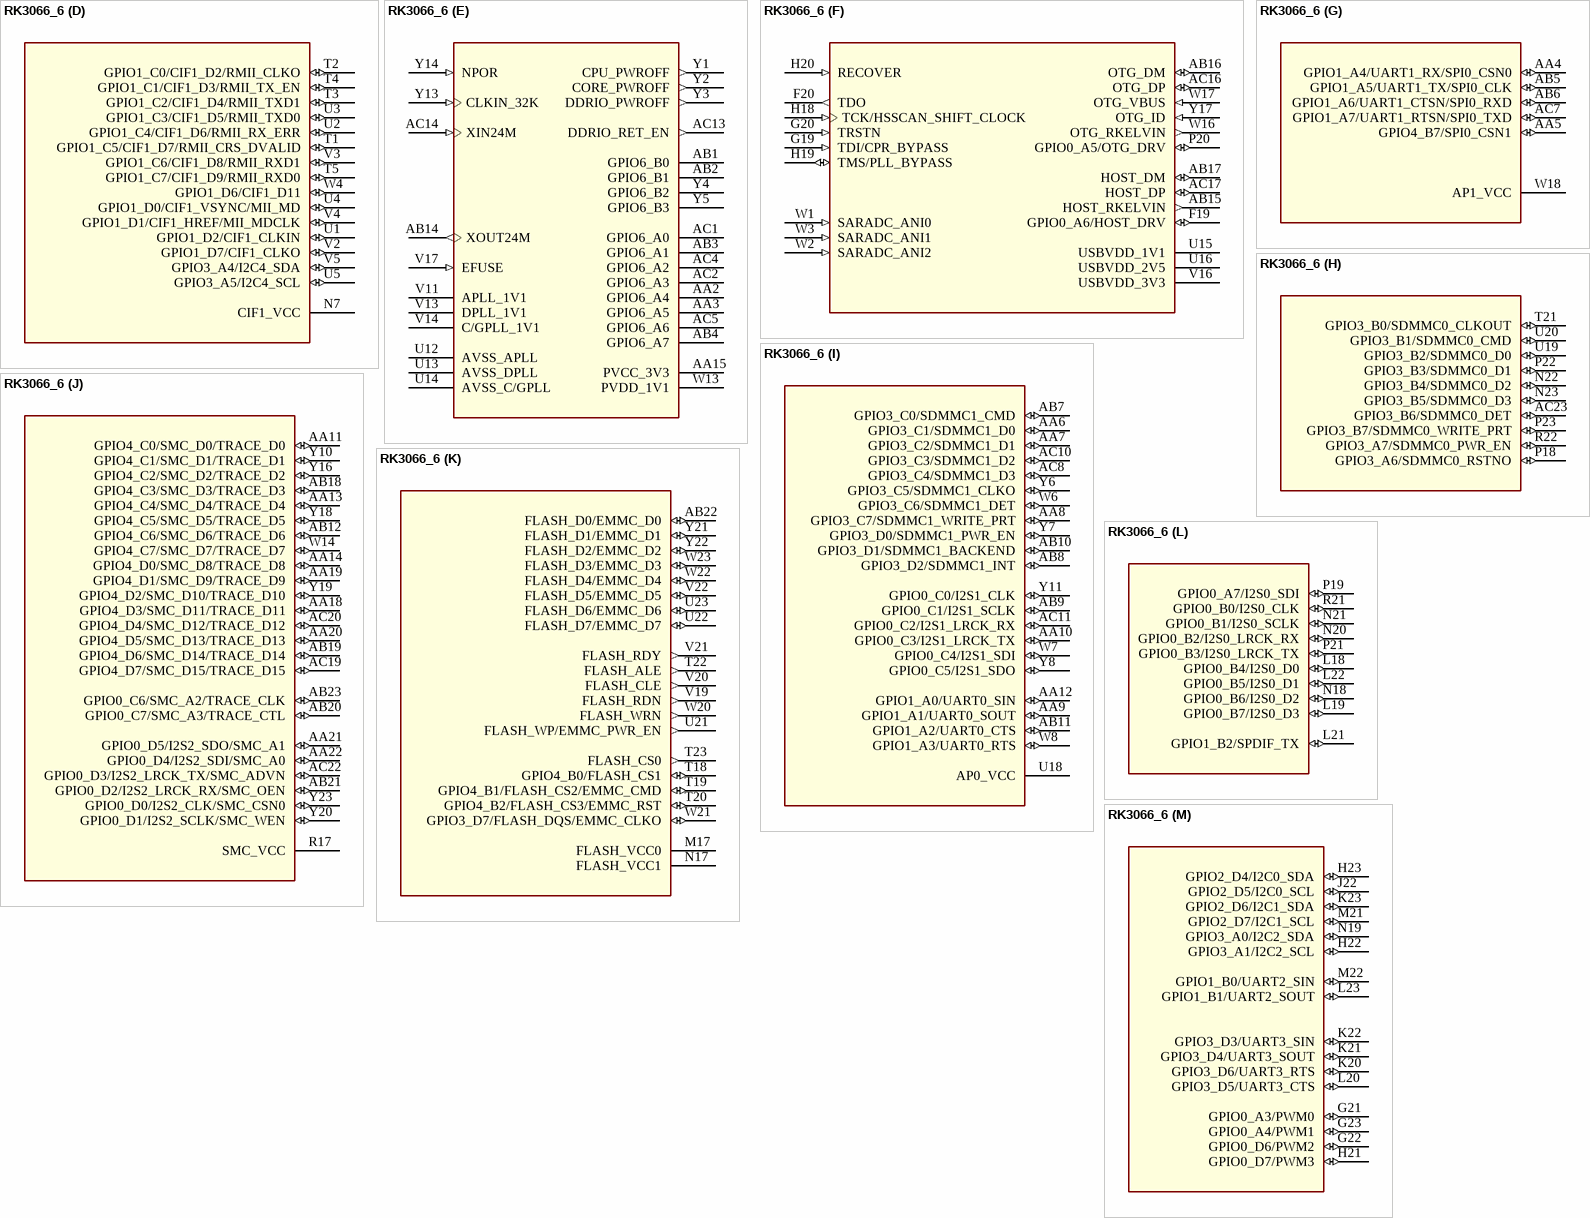
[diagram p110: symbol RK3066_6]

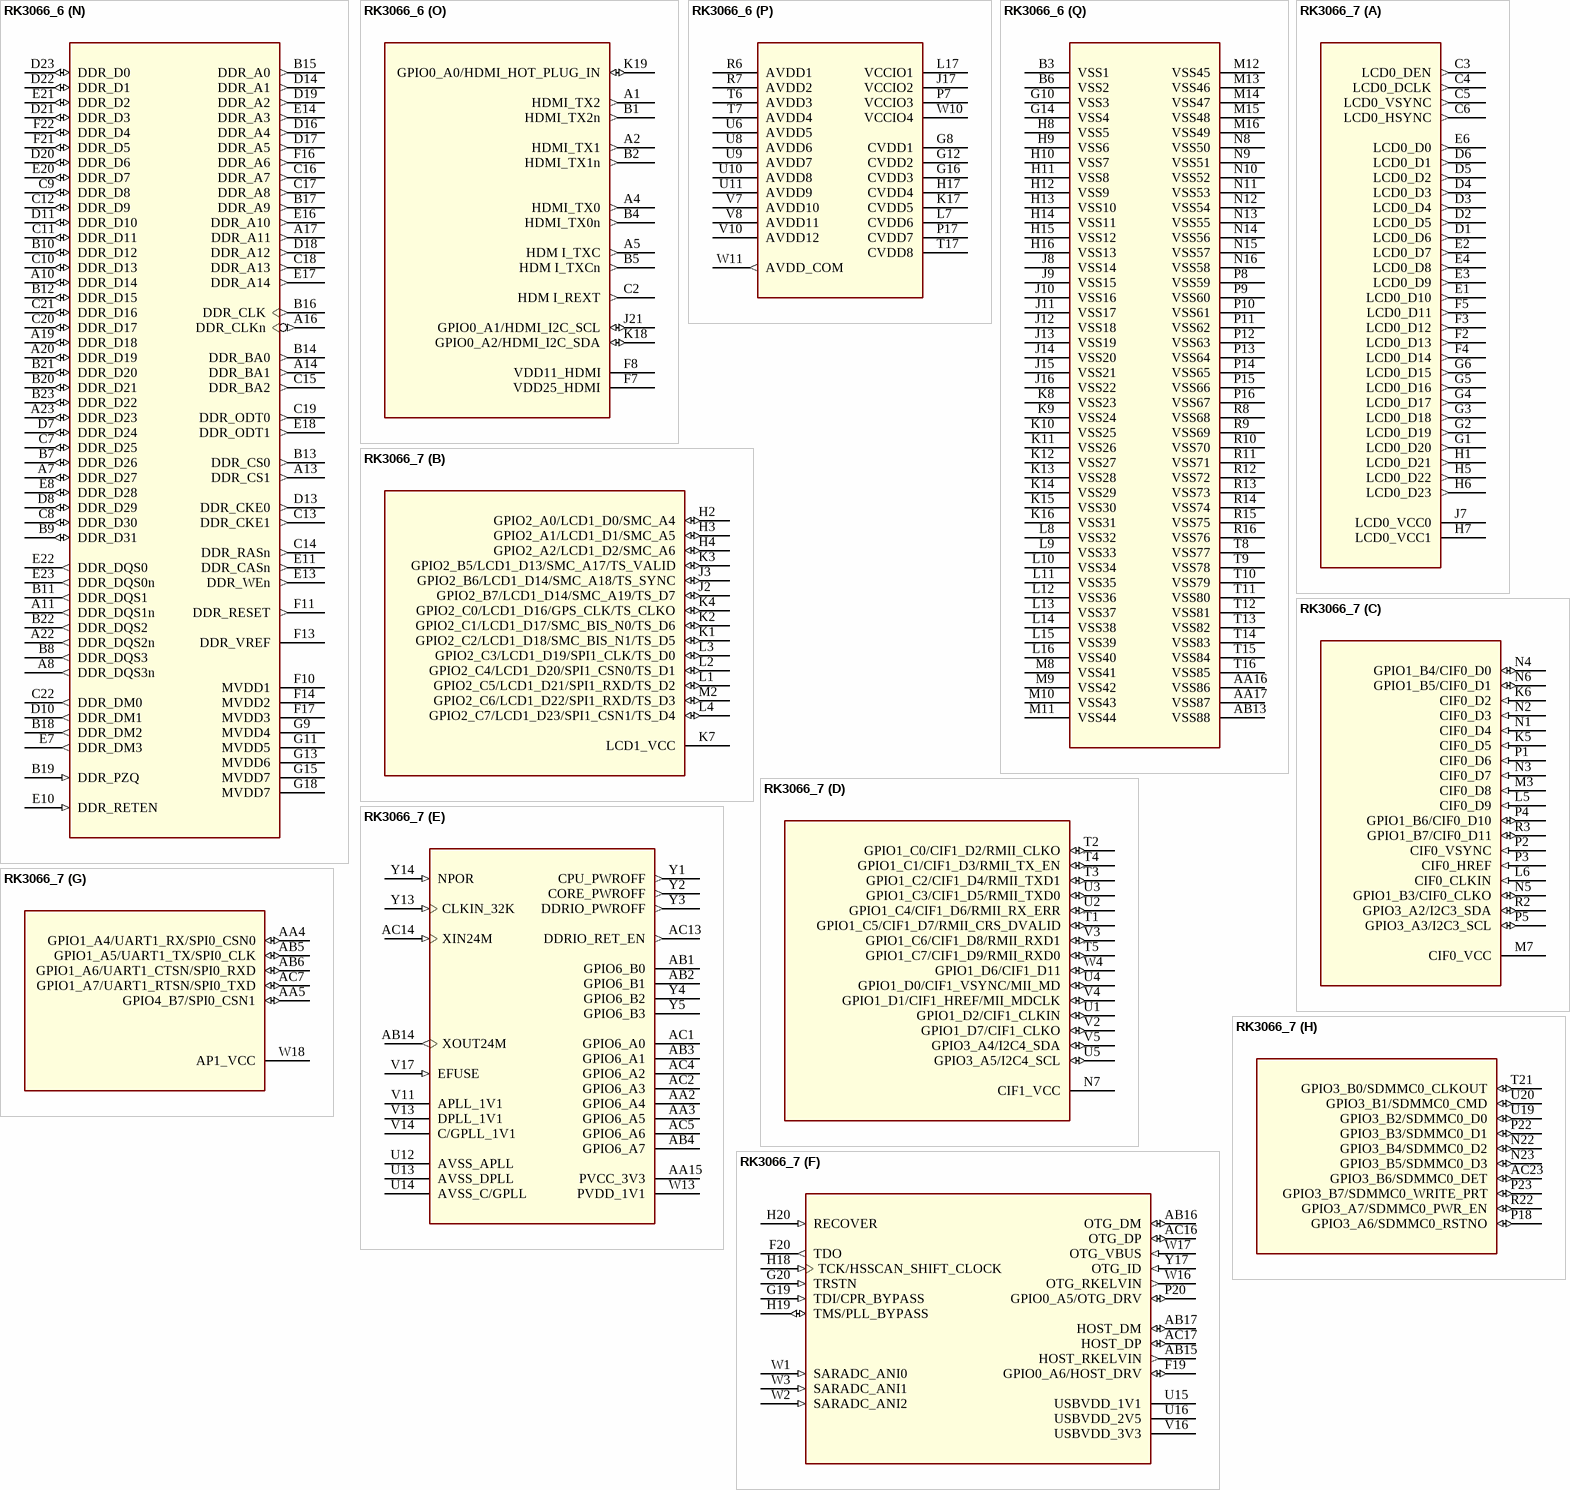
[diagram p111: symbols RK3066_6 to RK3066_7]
